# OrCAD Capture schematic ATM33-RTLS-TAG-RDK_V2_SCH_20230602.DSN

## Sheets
1 01. TITLE: title: ATM33-RTLS-TAG-RDK; rev: 0; note: <076-11-610-xxxx>
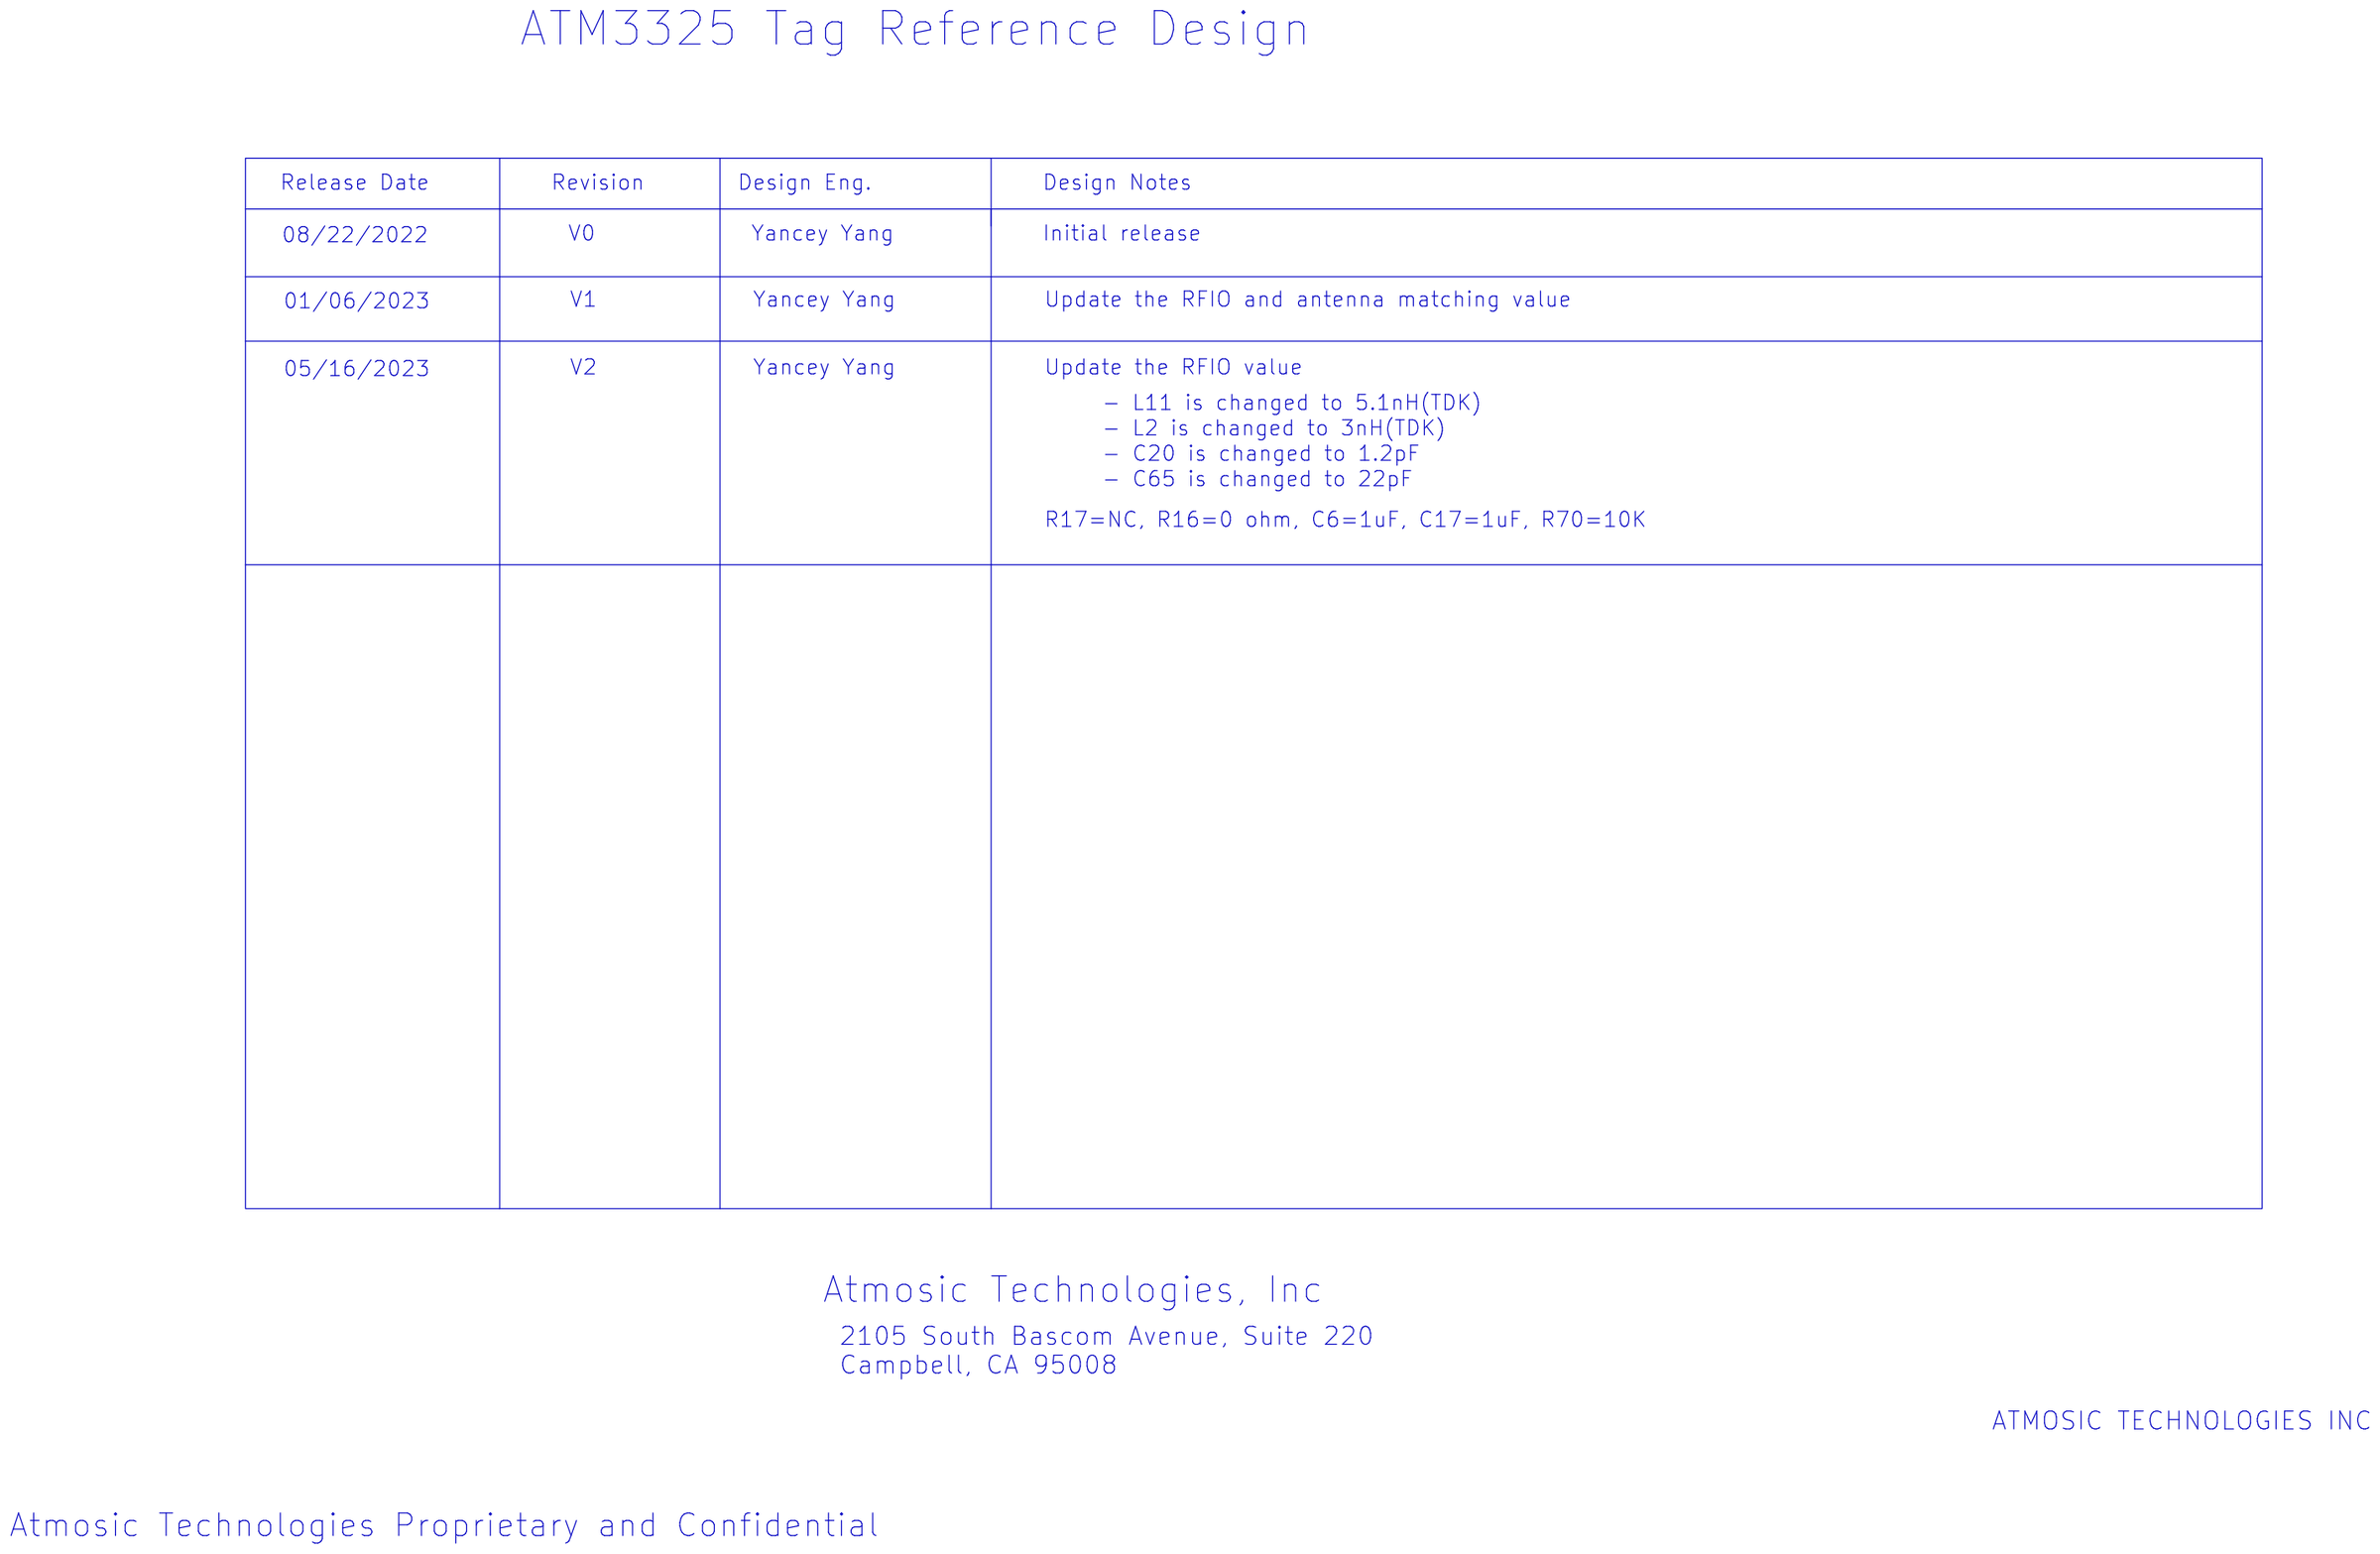
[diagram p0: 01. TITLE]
2 02_Block overall
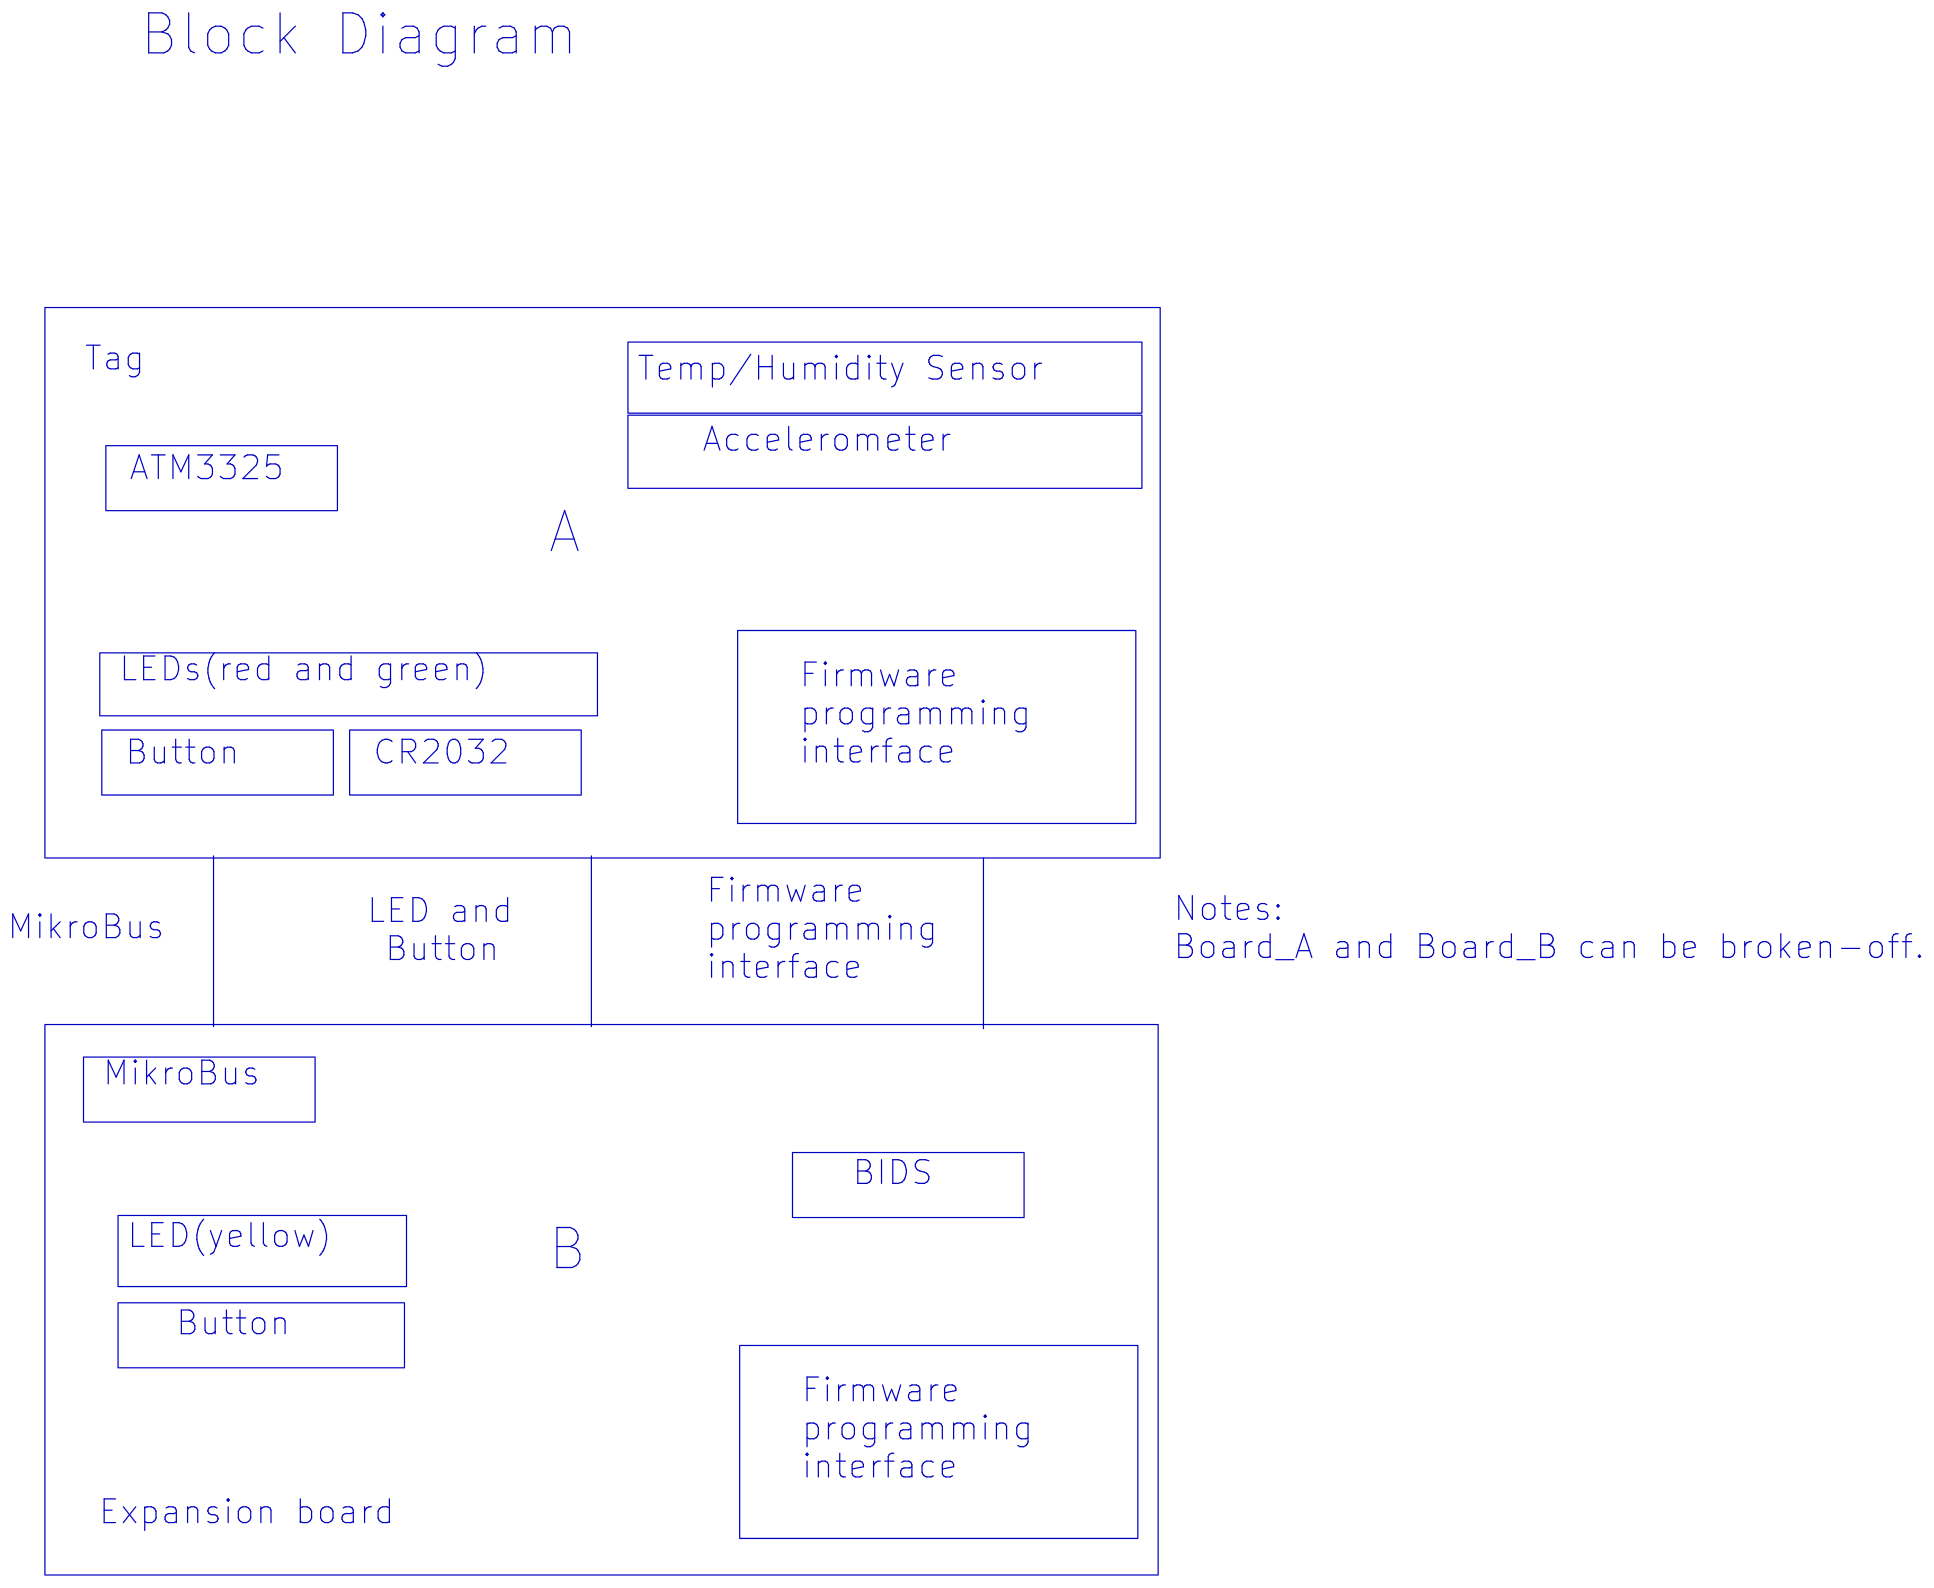
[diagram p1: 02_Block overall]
3 03. Block Diagram A
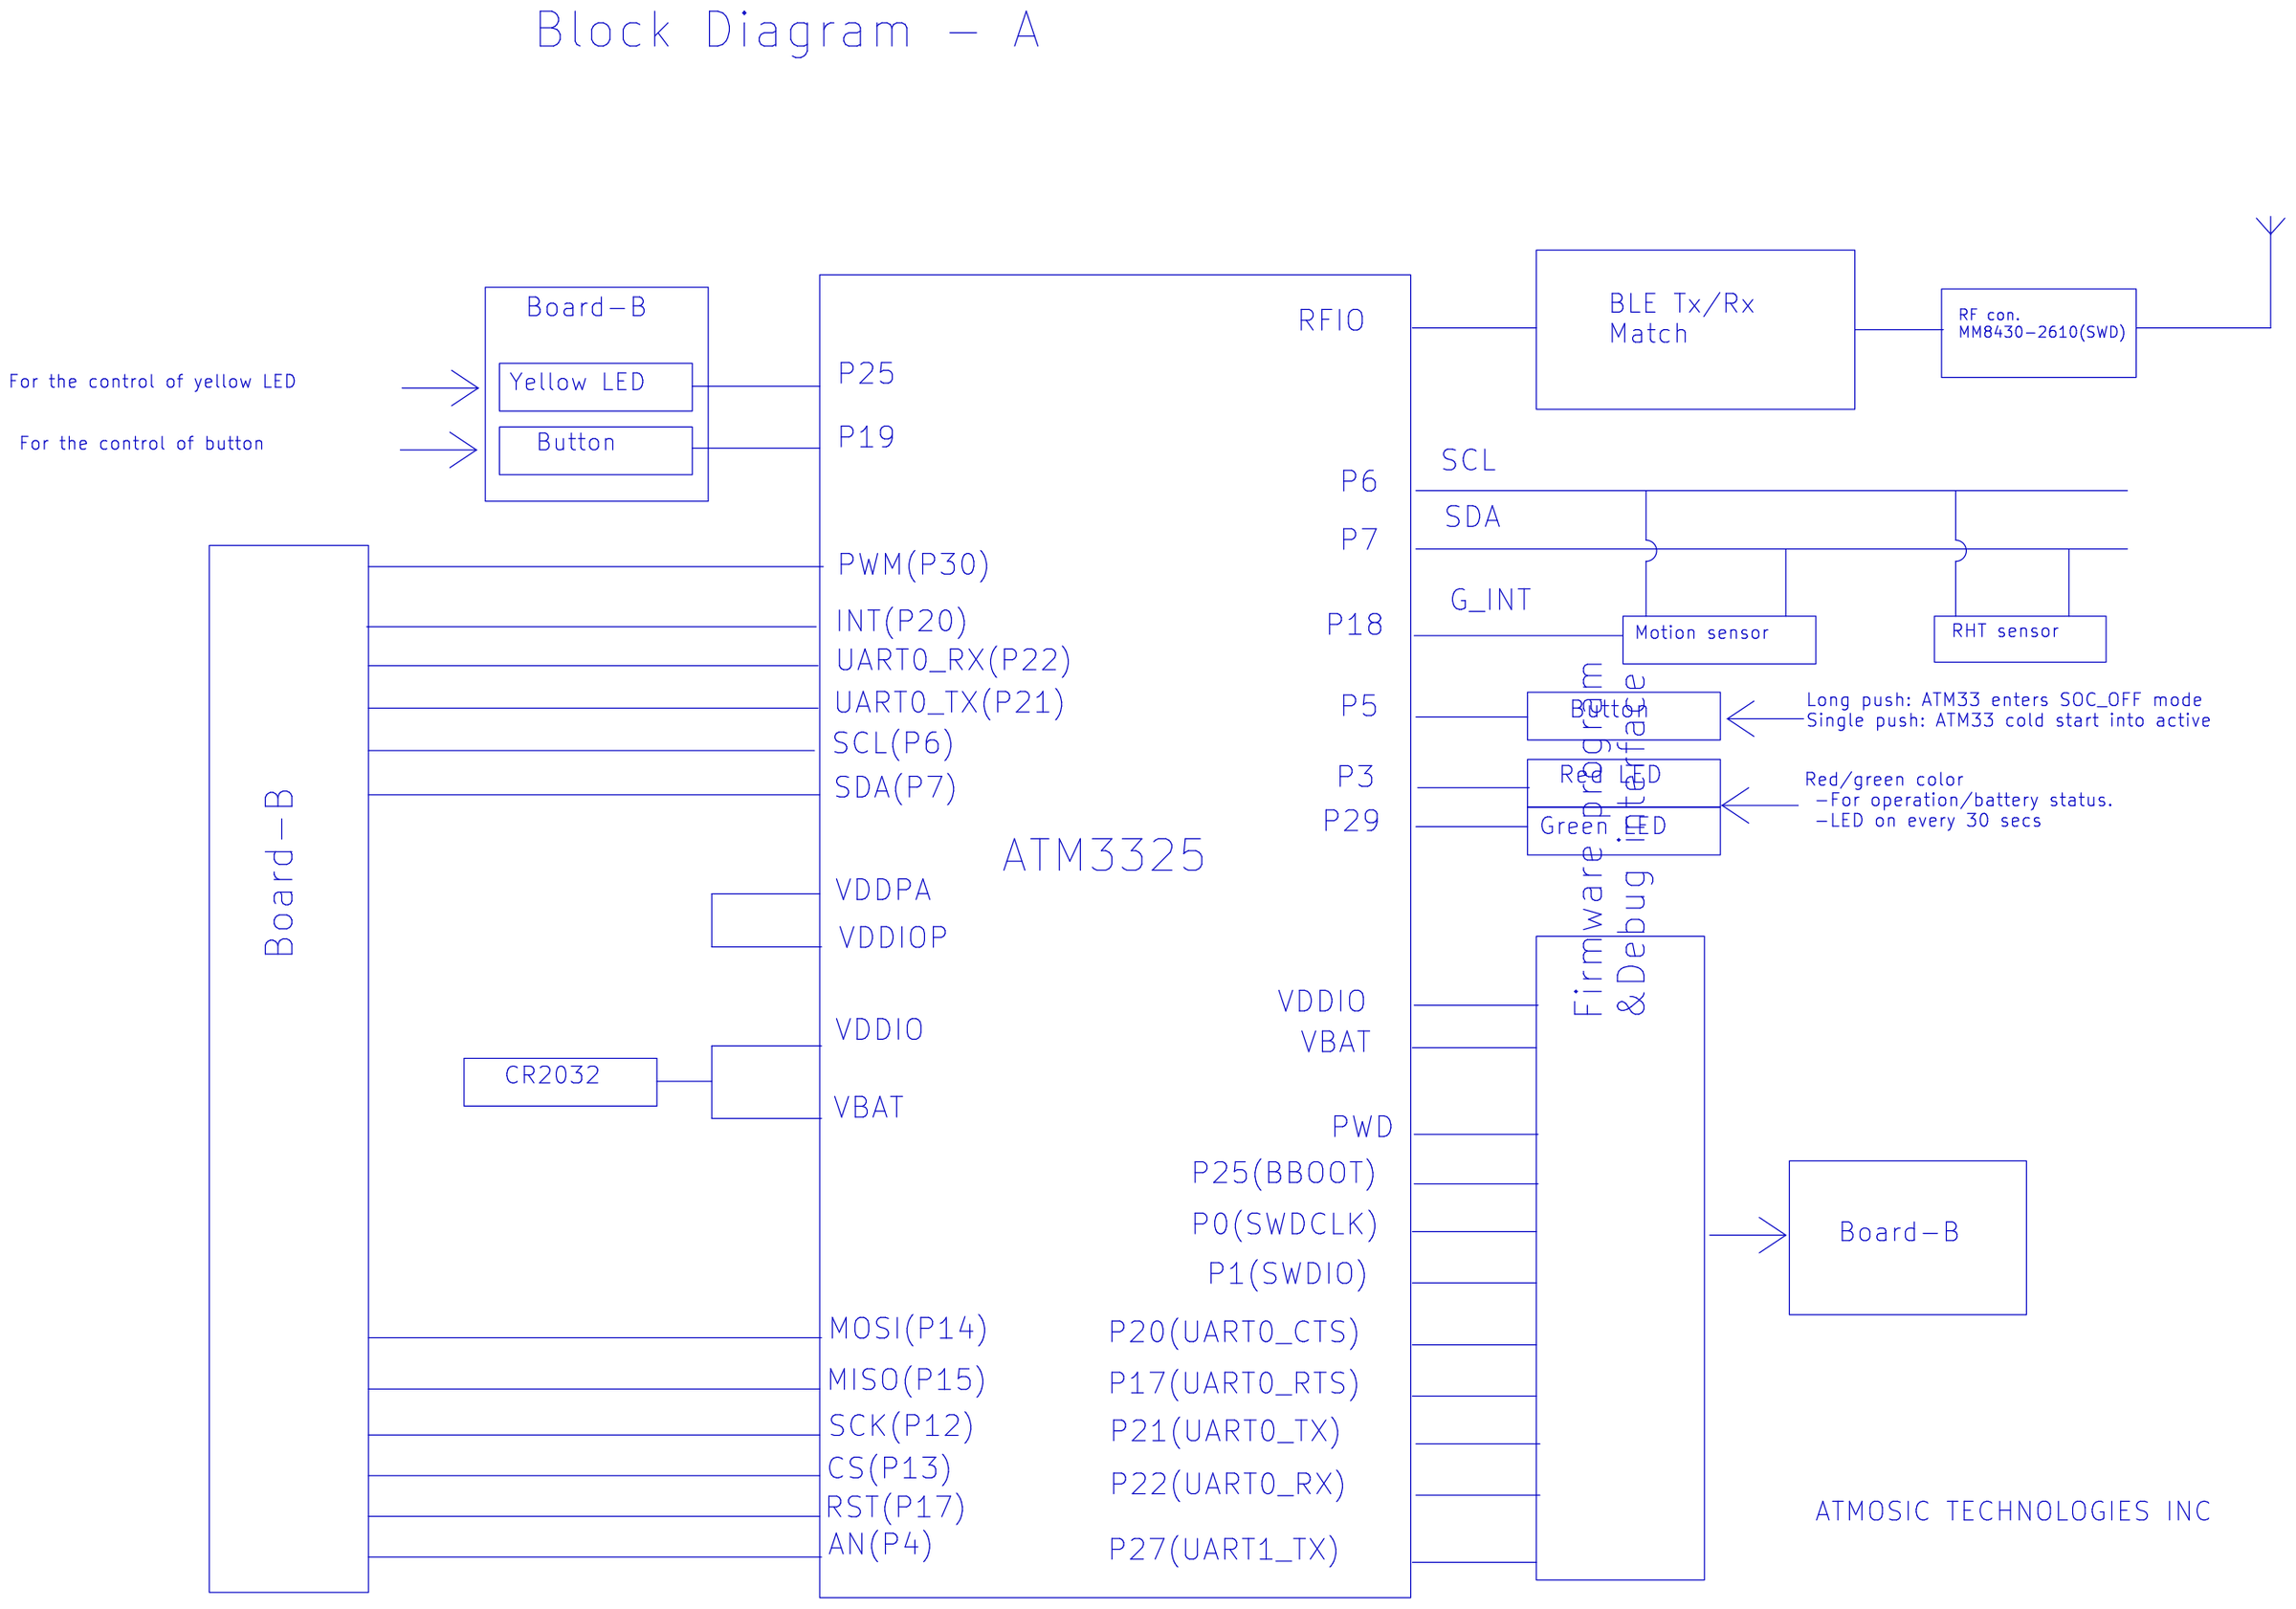
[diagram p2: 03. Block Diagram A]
4 04_Block Diagram B
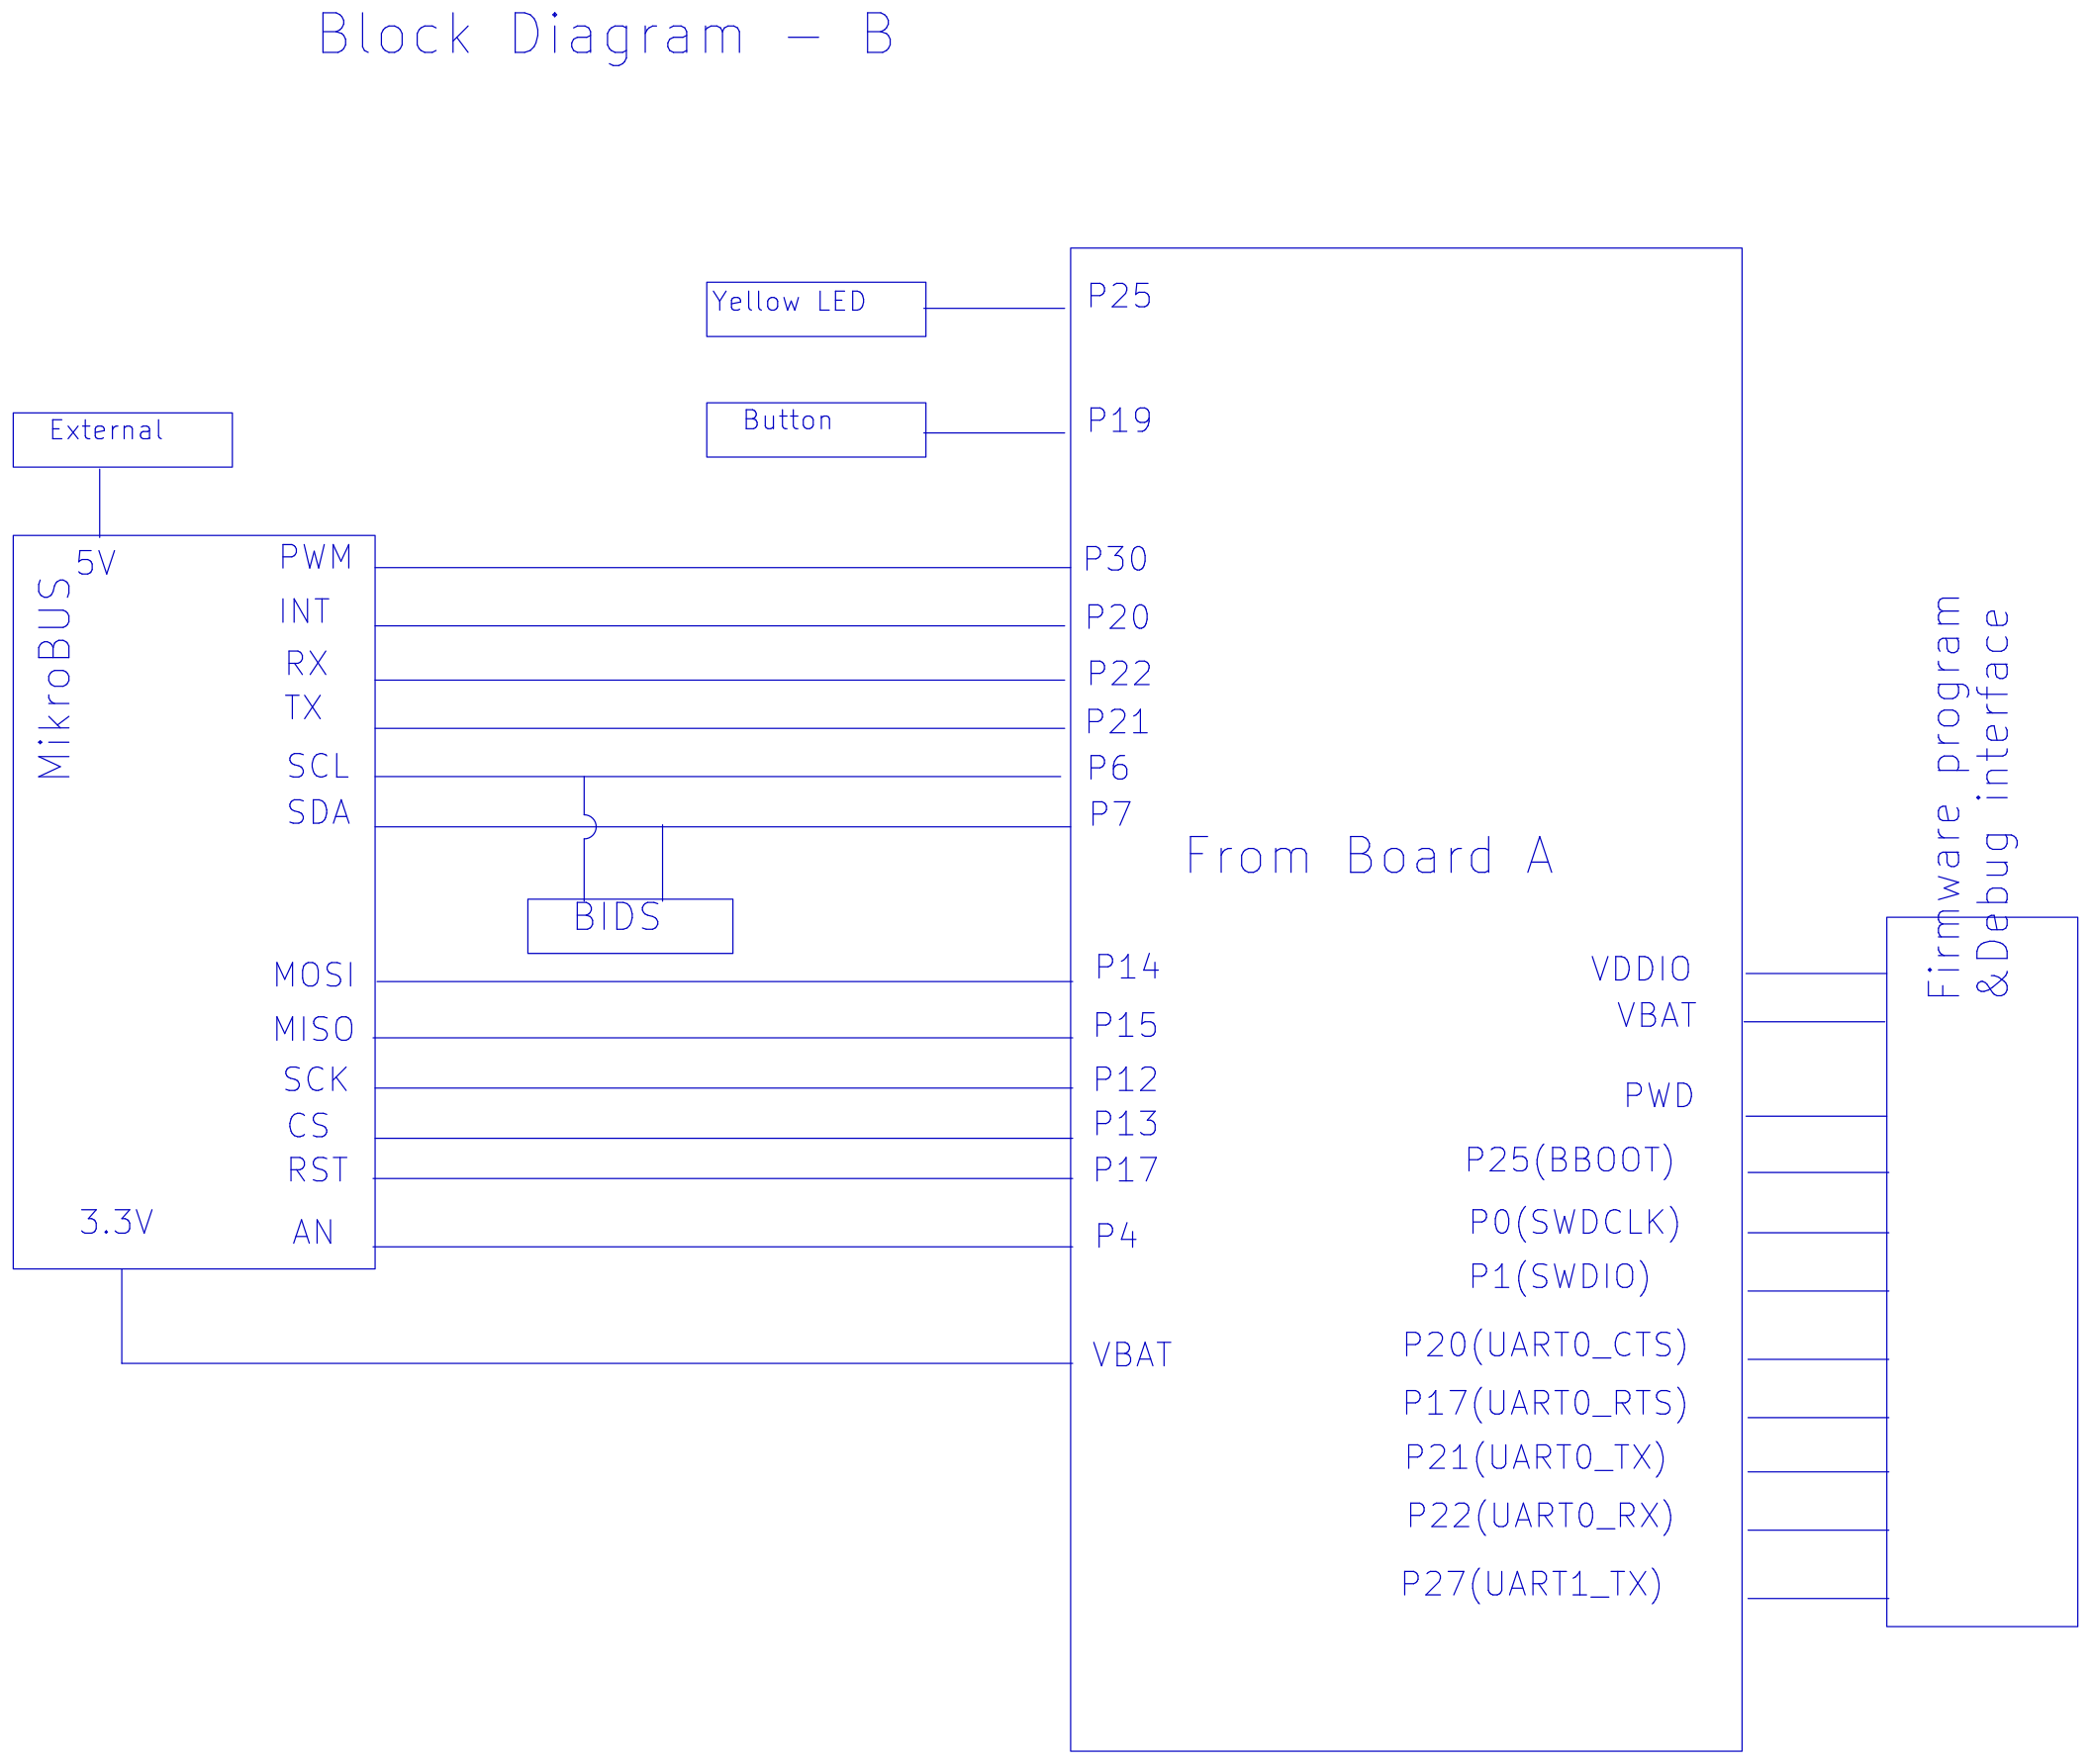
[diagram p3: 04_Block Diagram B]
5 05. ATM3325: size B; rev: 2
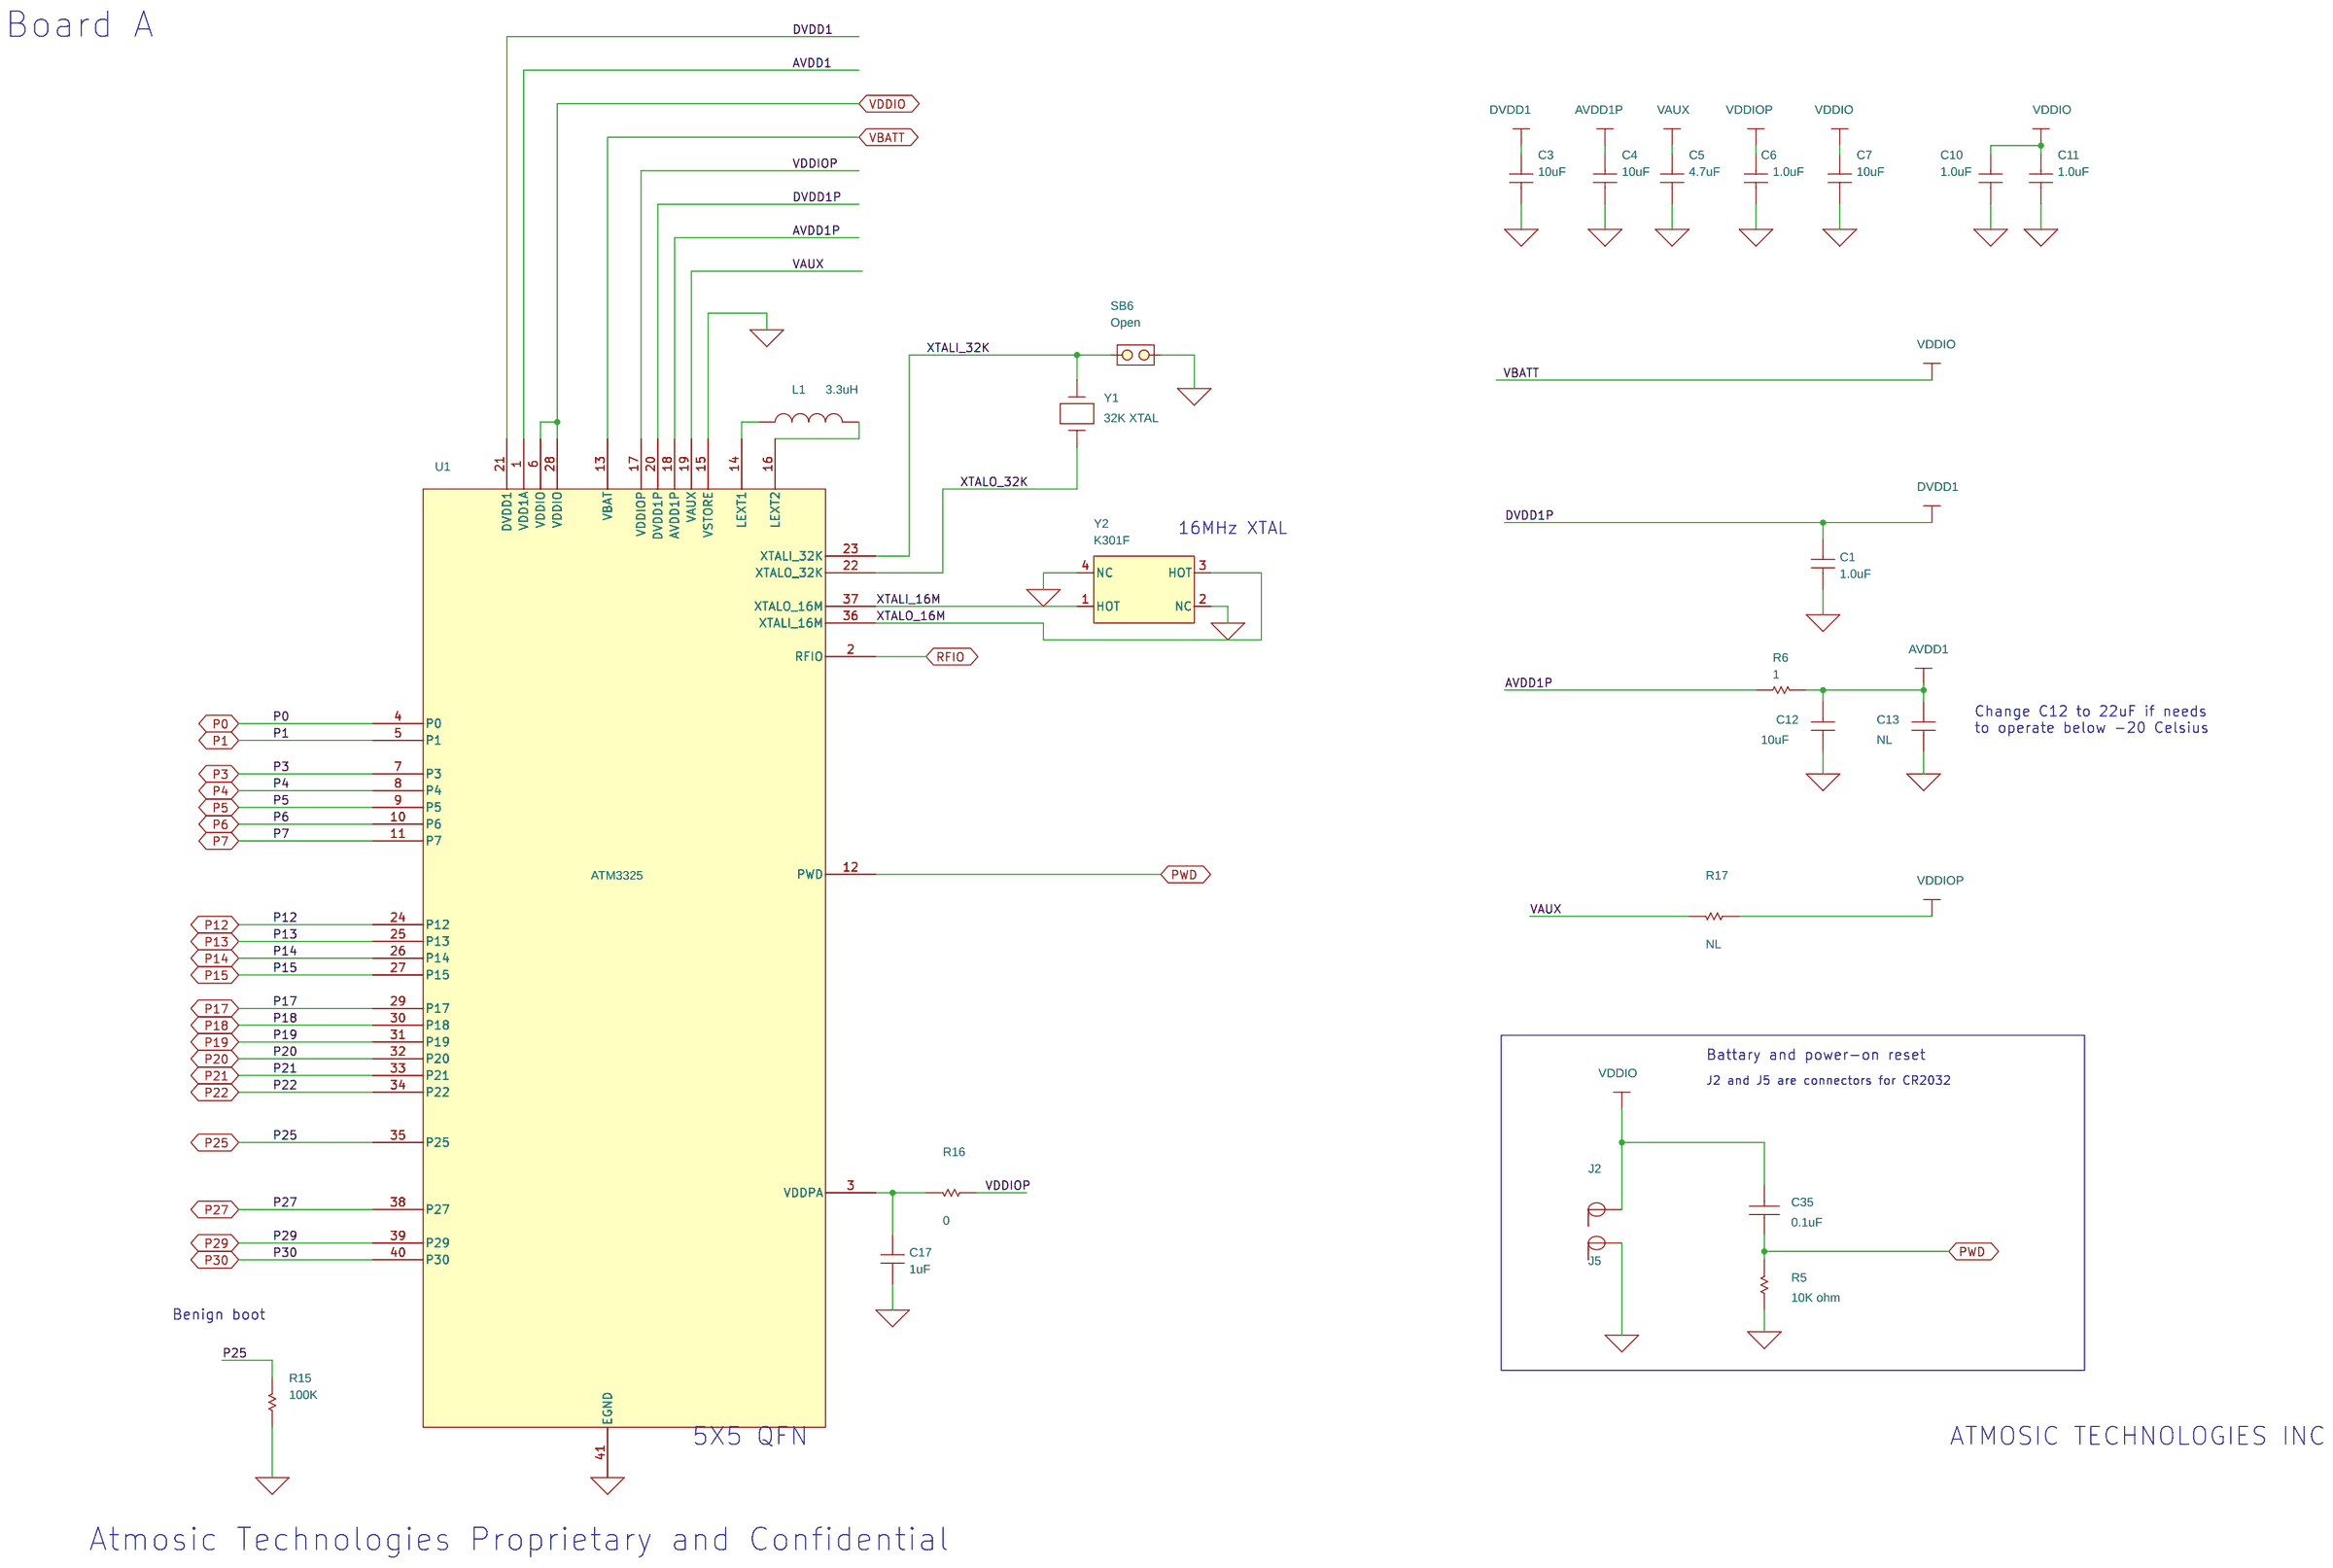
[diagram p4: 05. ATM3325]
6 06. RF (RFIO): size B
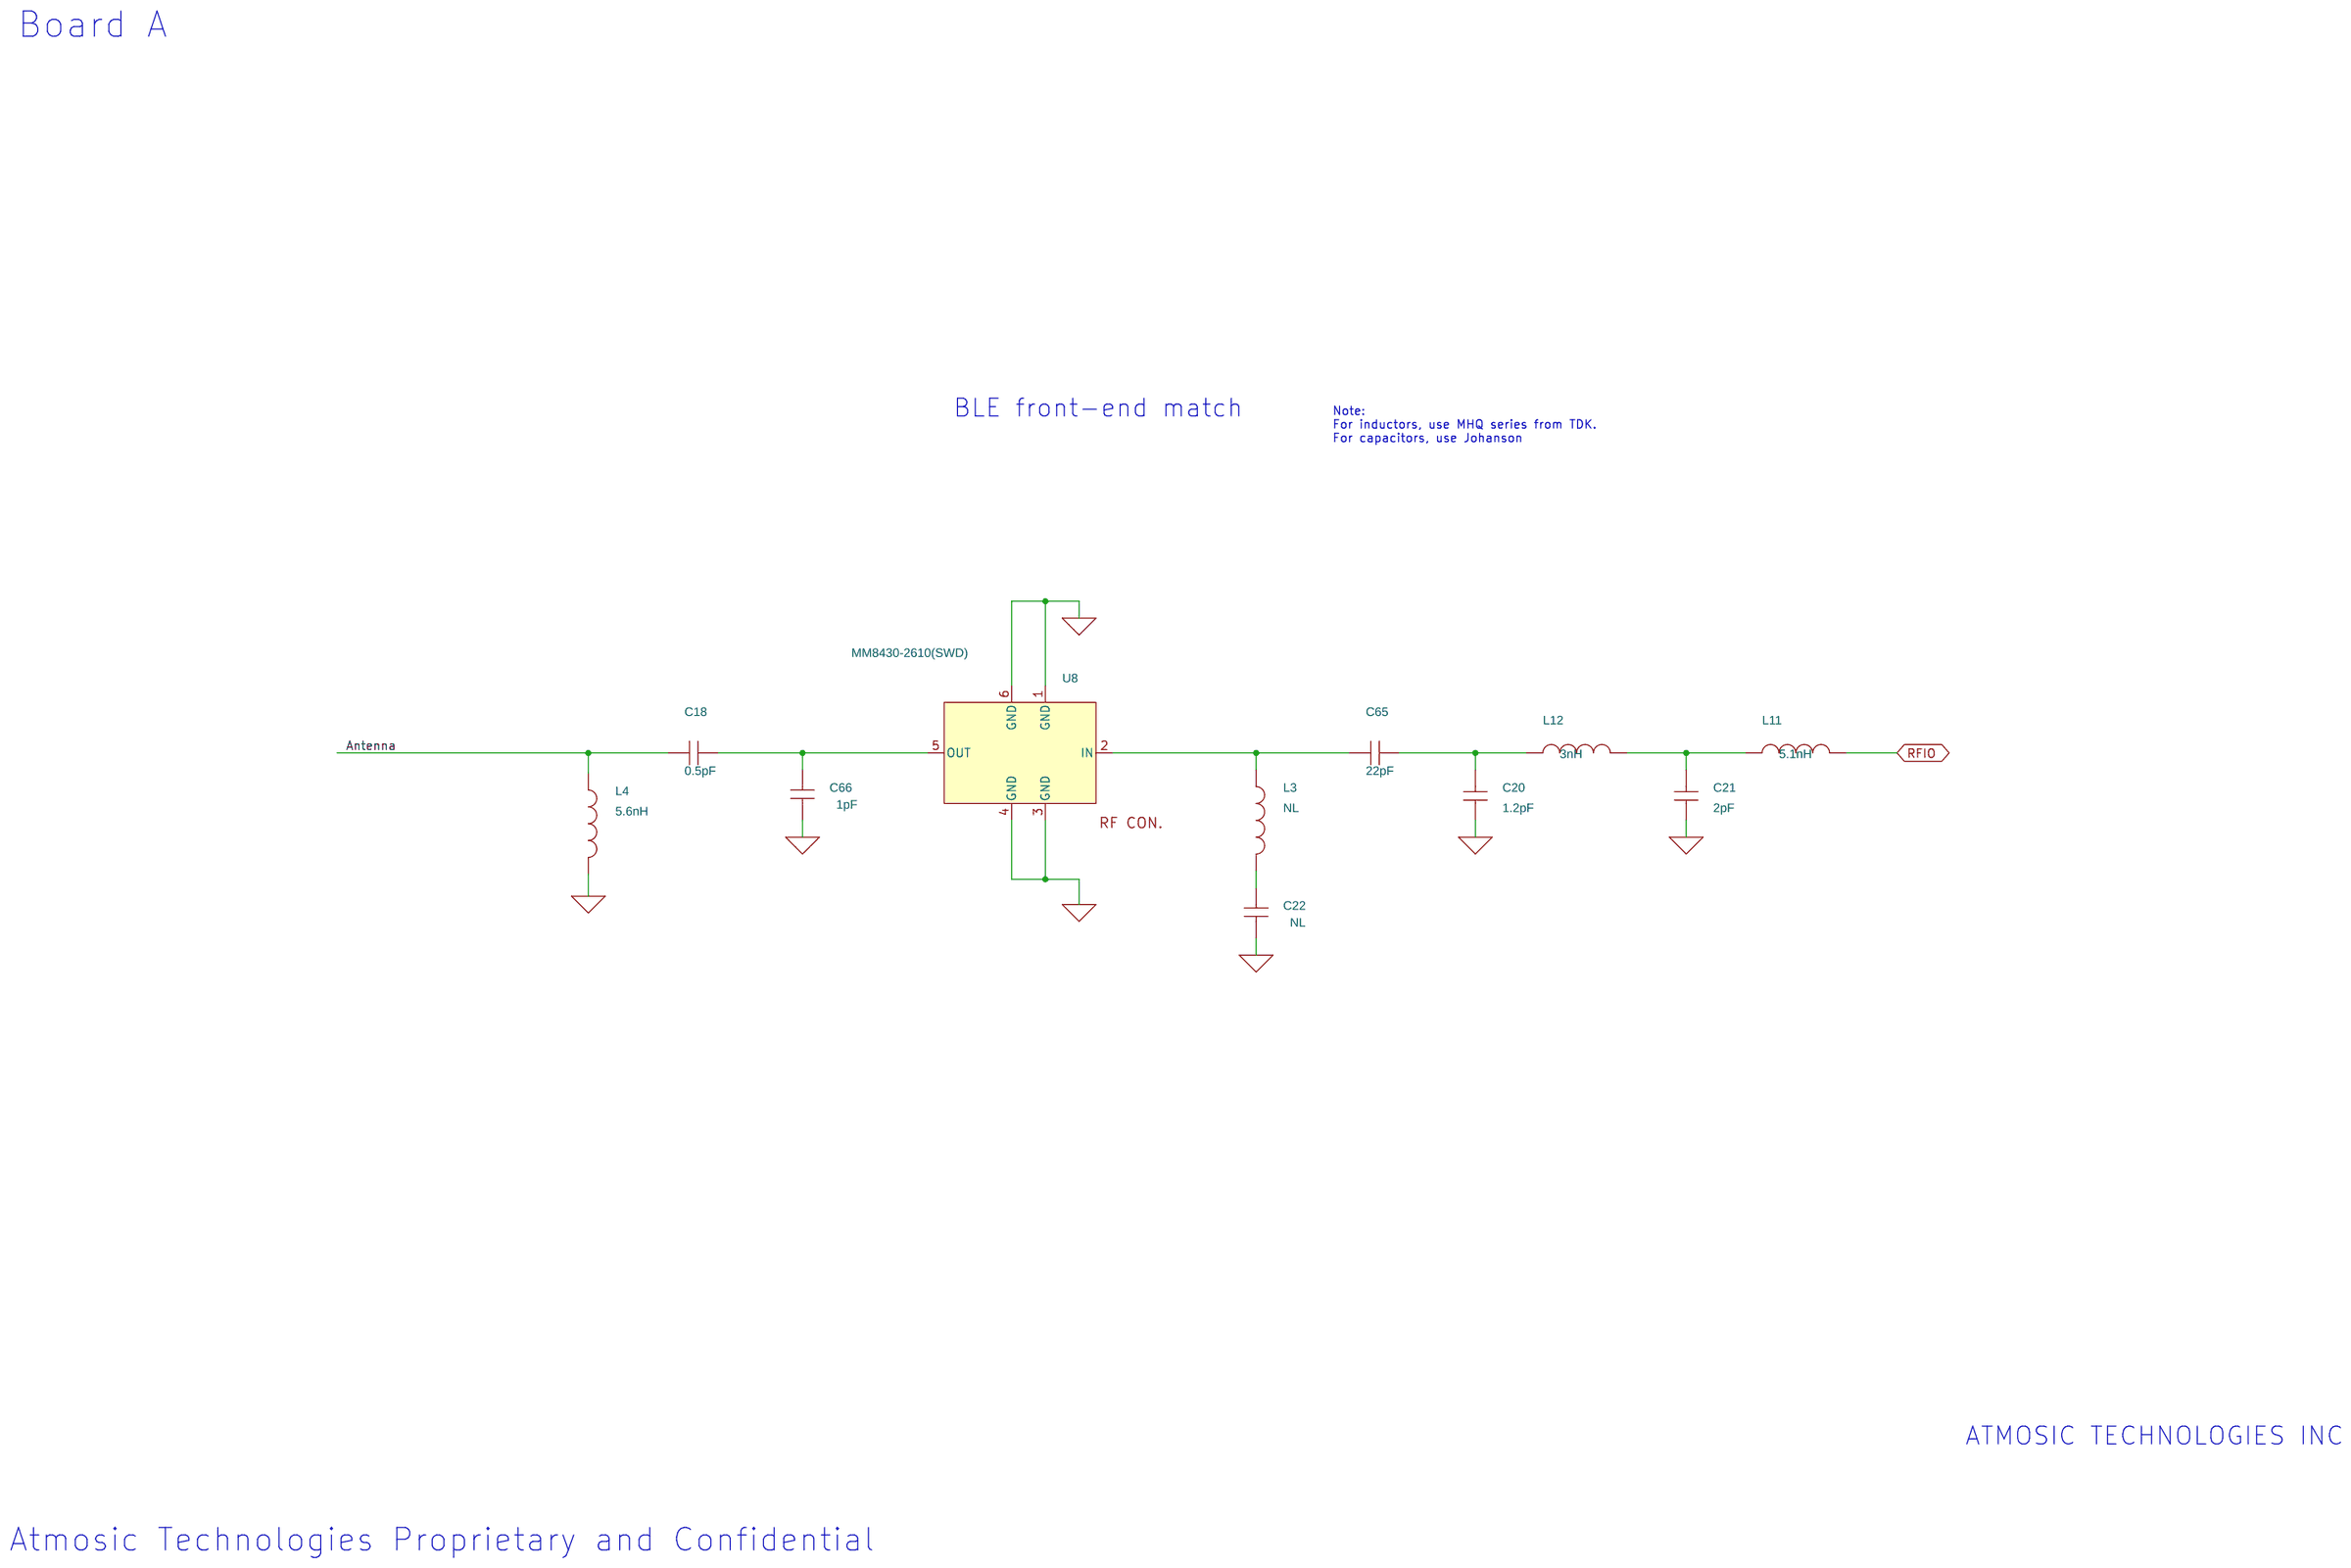
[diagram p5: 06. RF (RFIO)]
7 07. Buttons LEDs Sensors: size B
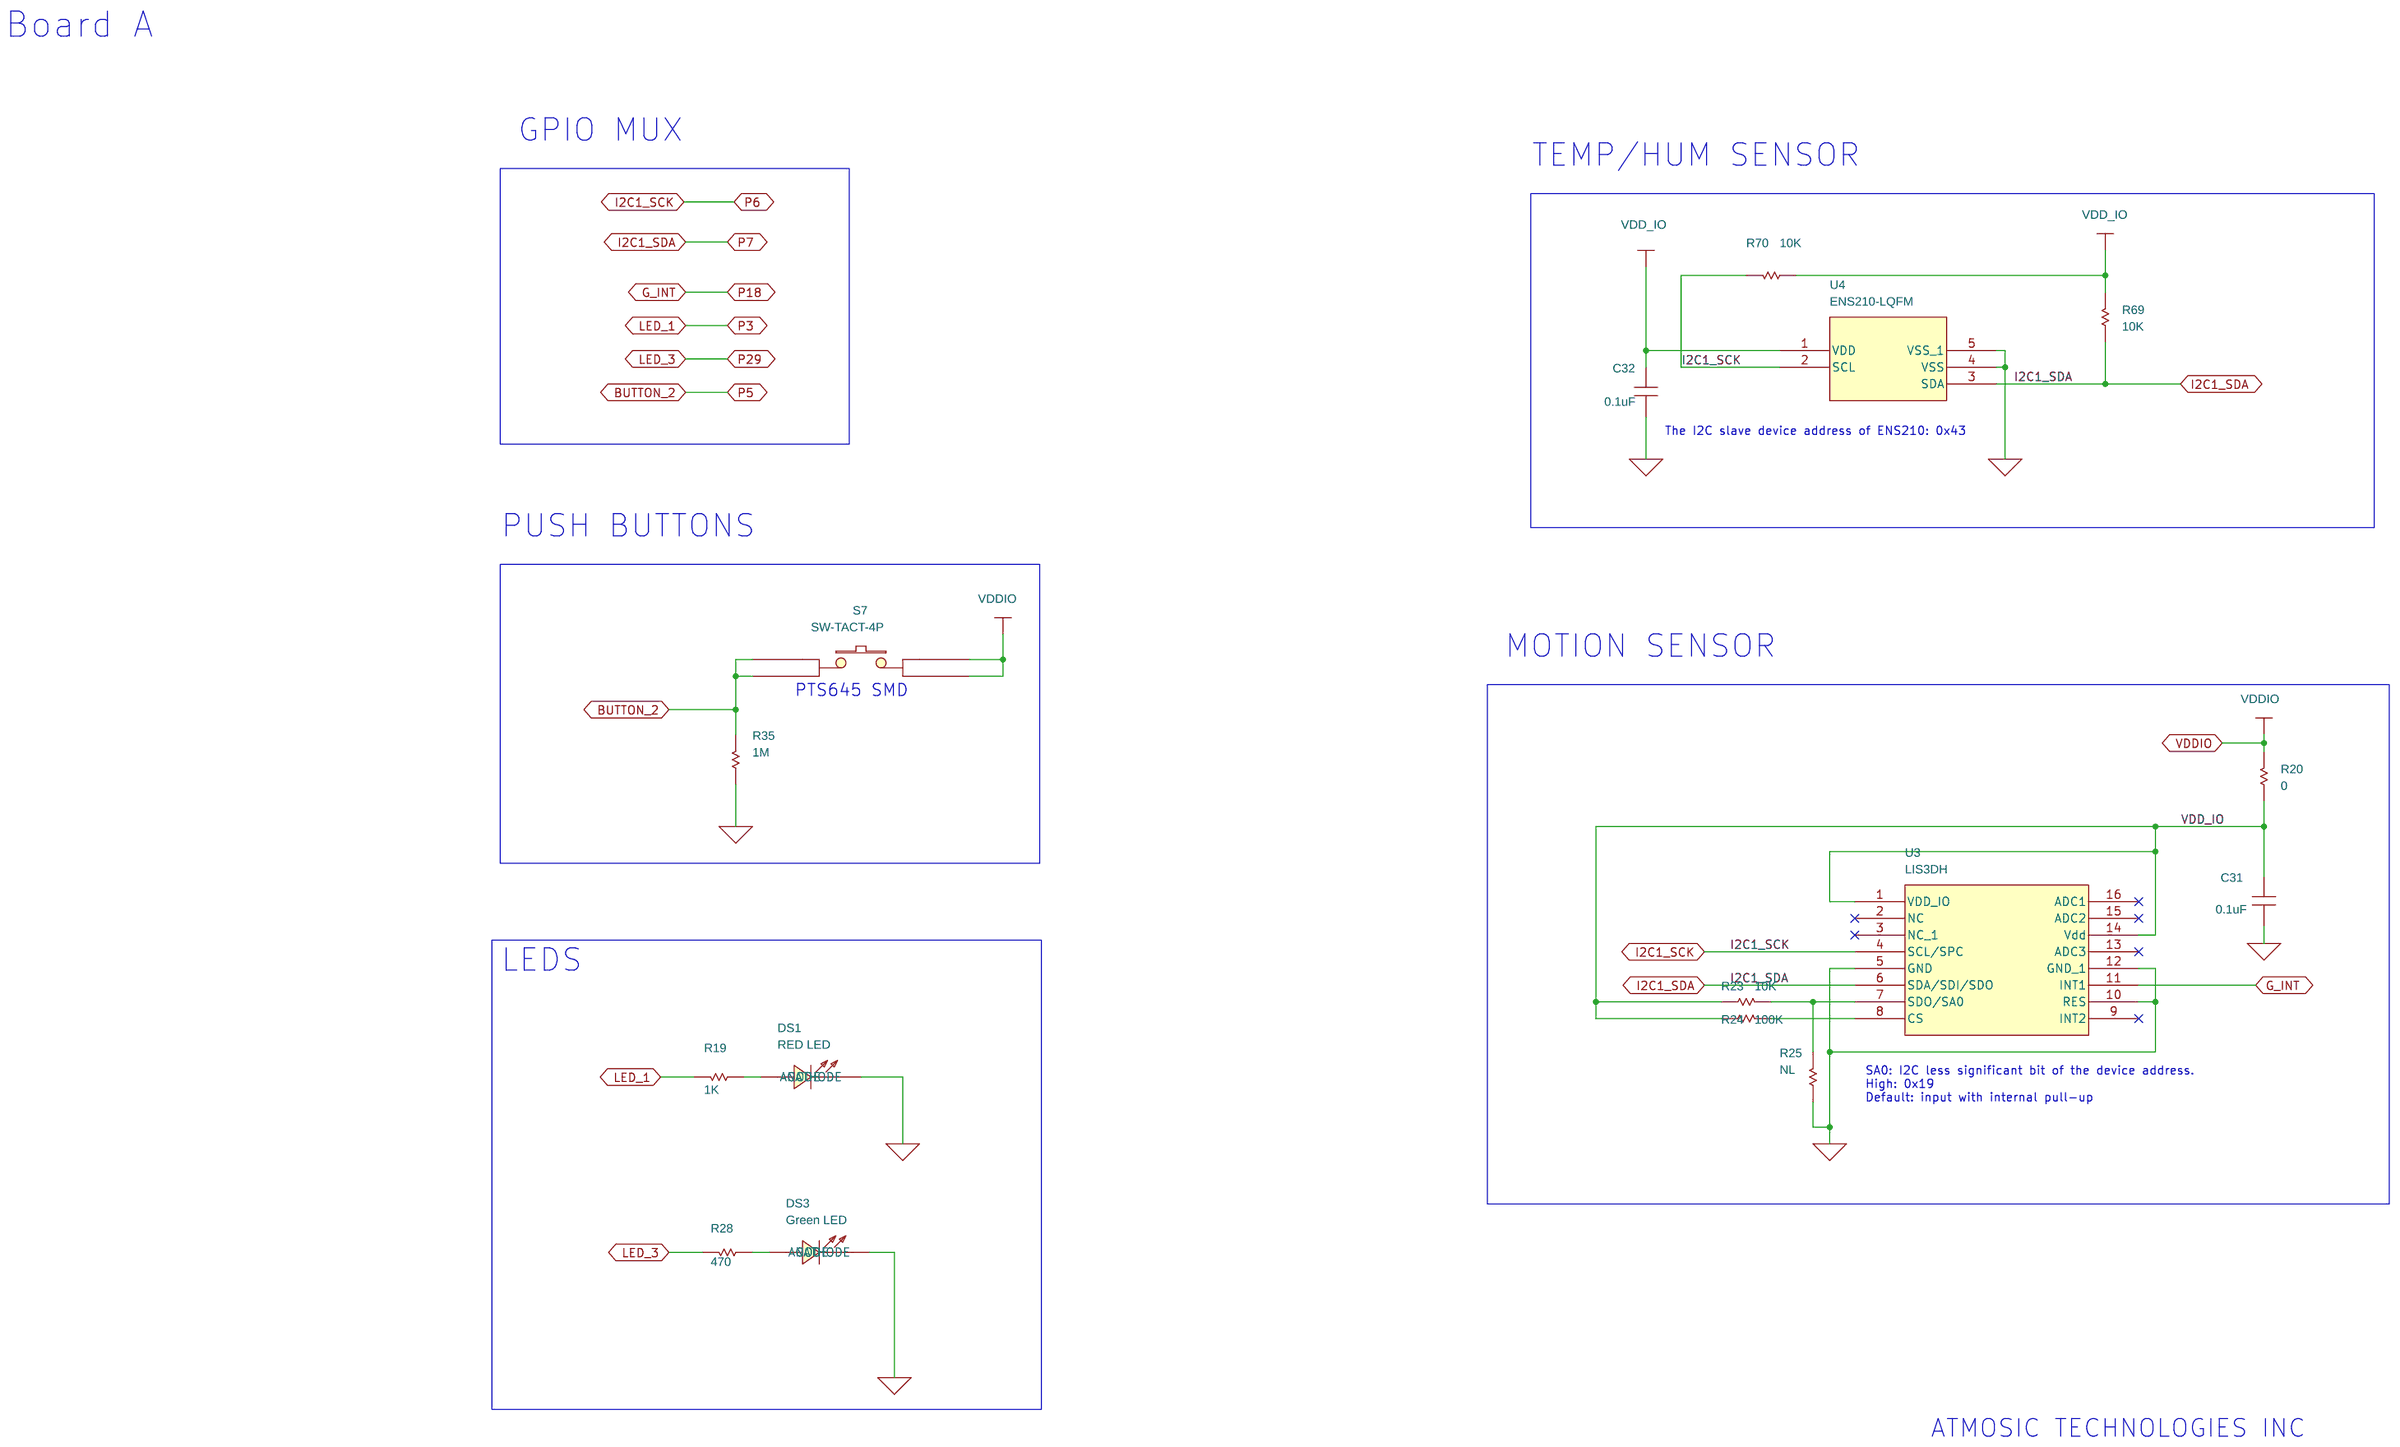
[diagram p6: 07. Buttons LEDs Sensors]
8 08. Board_A_Connectors: size B
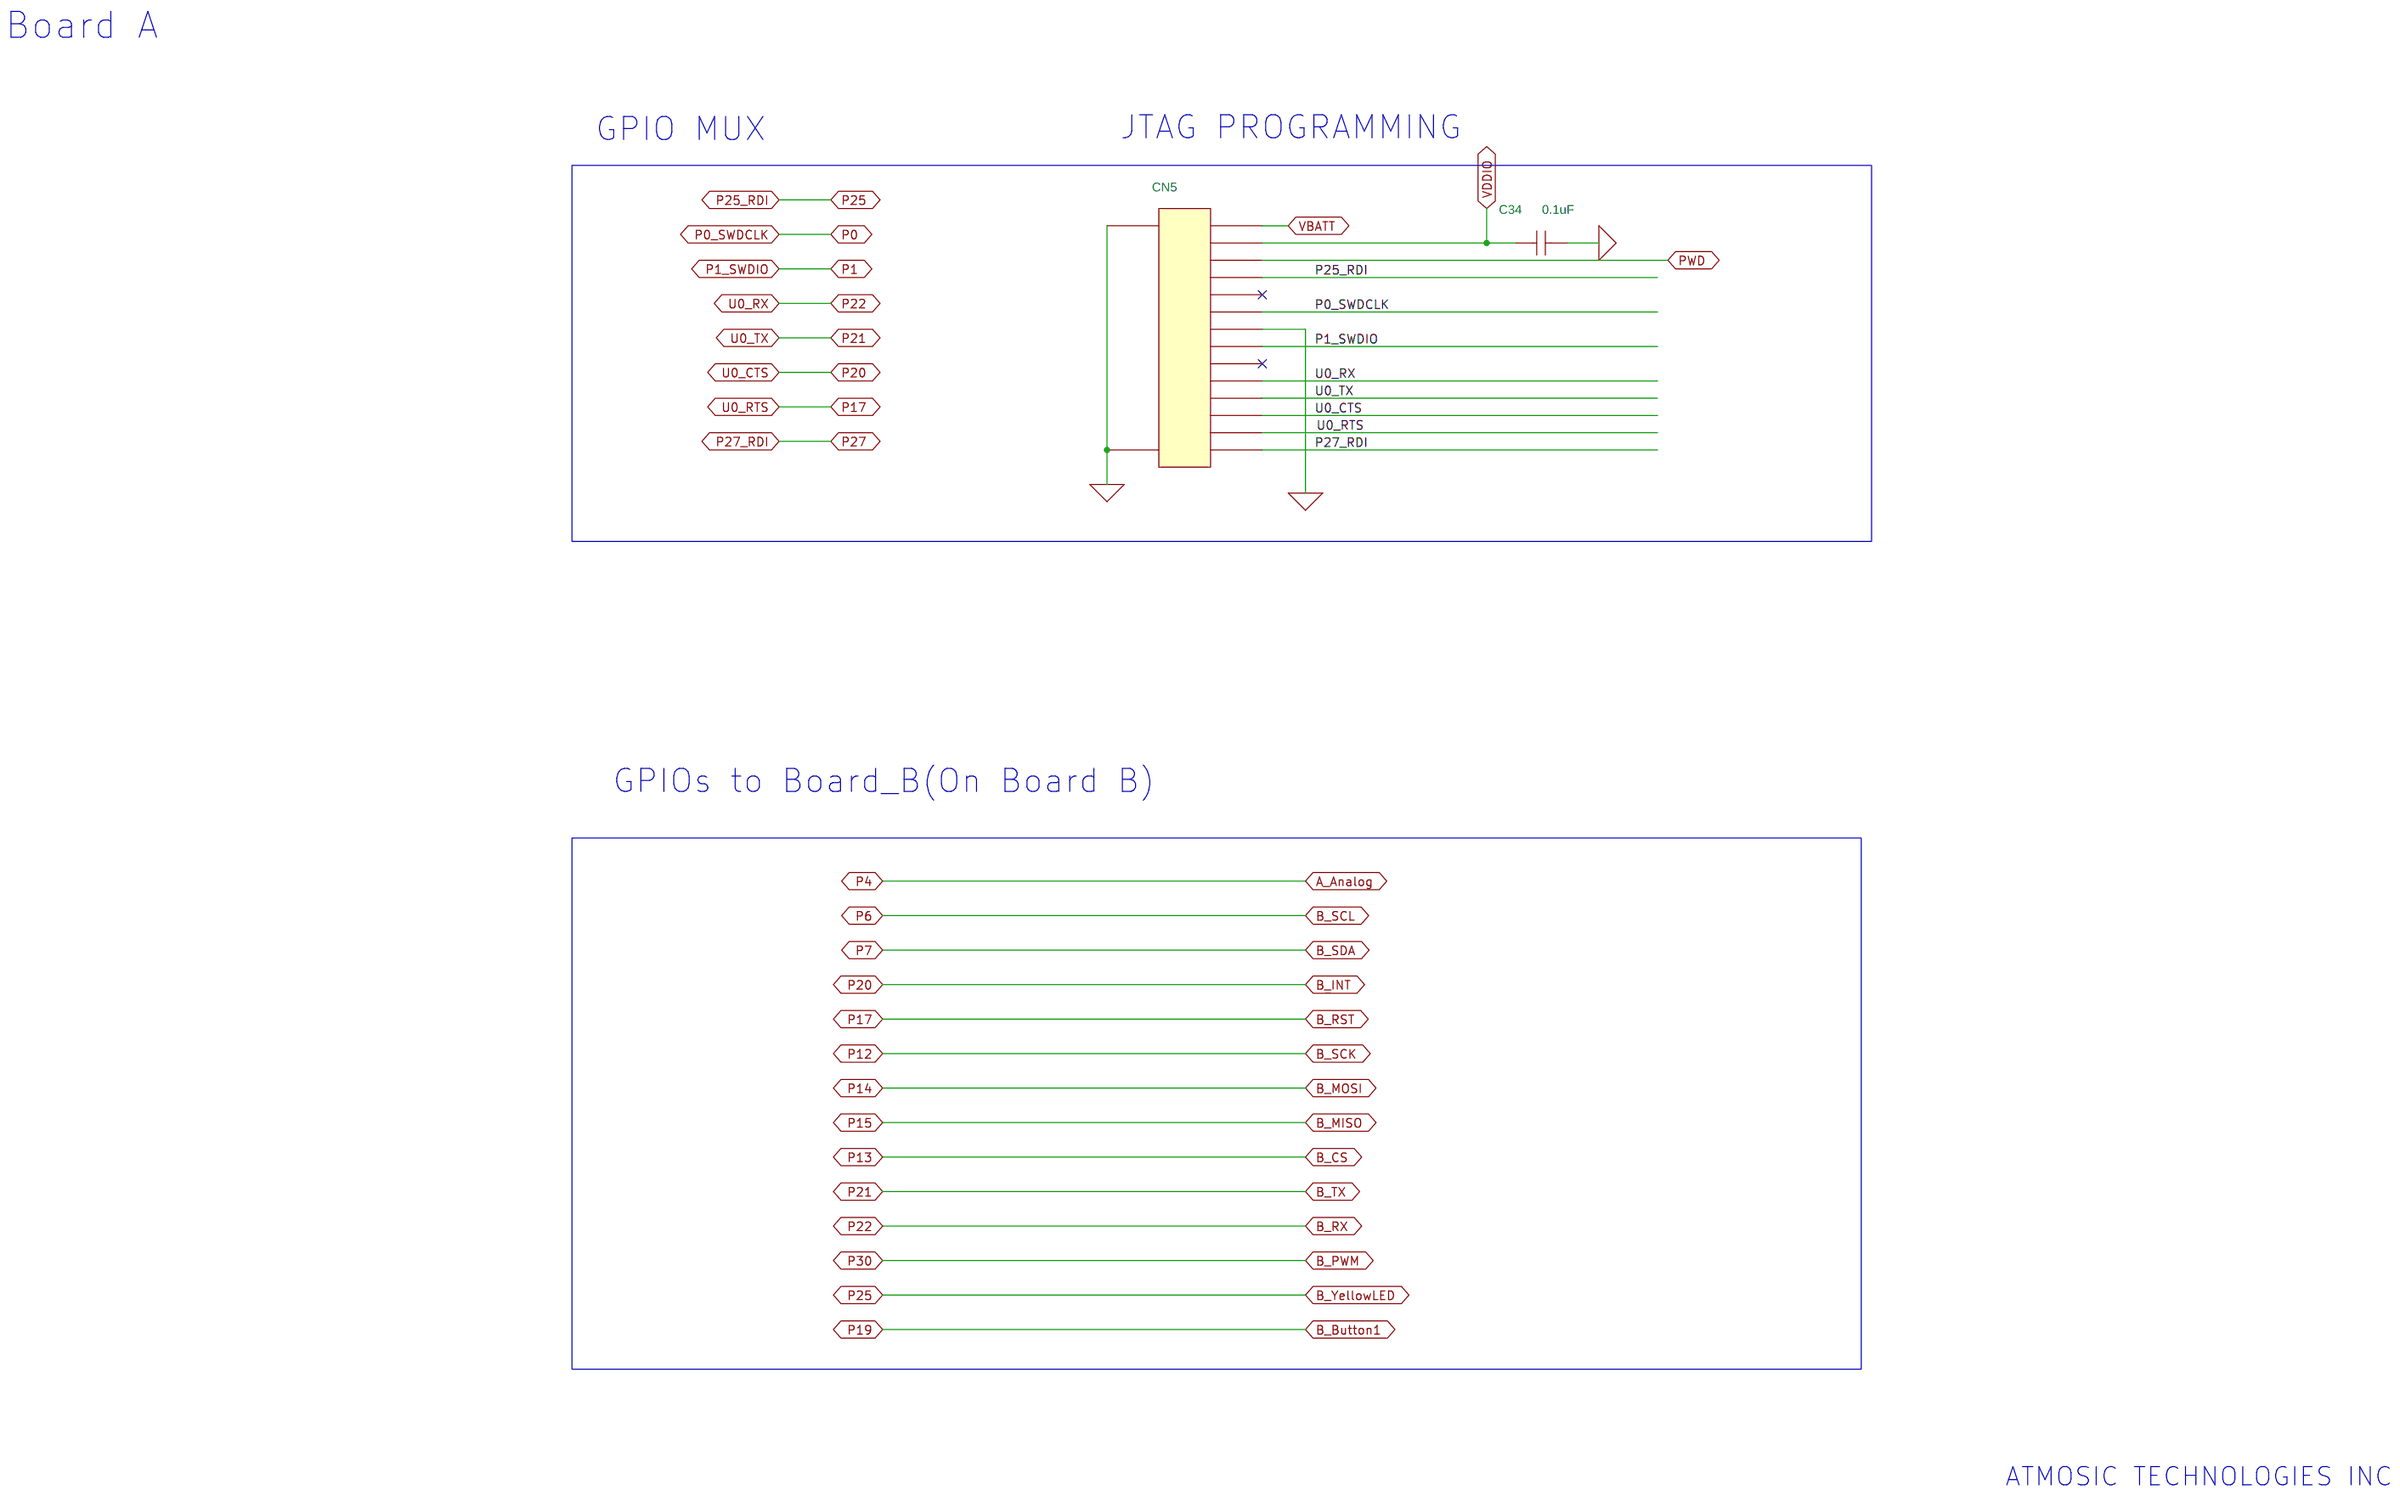
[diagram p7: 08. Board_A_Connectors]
9 09_Board_B-LEDs Buttons Sensors: size B
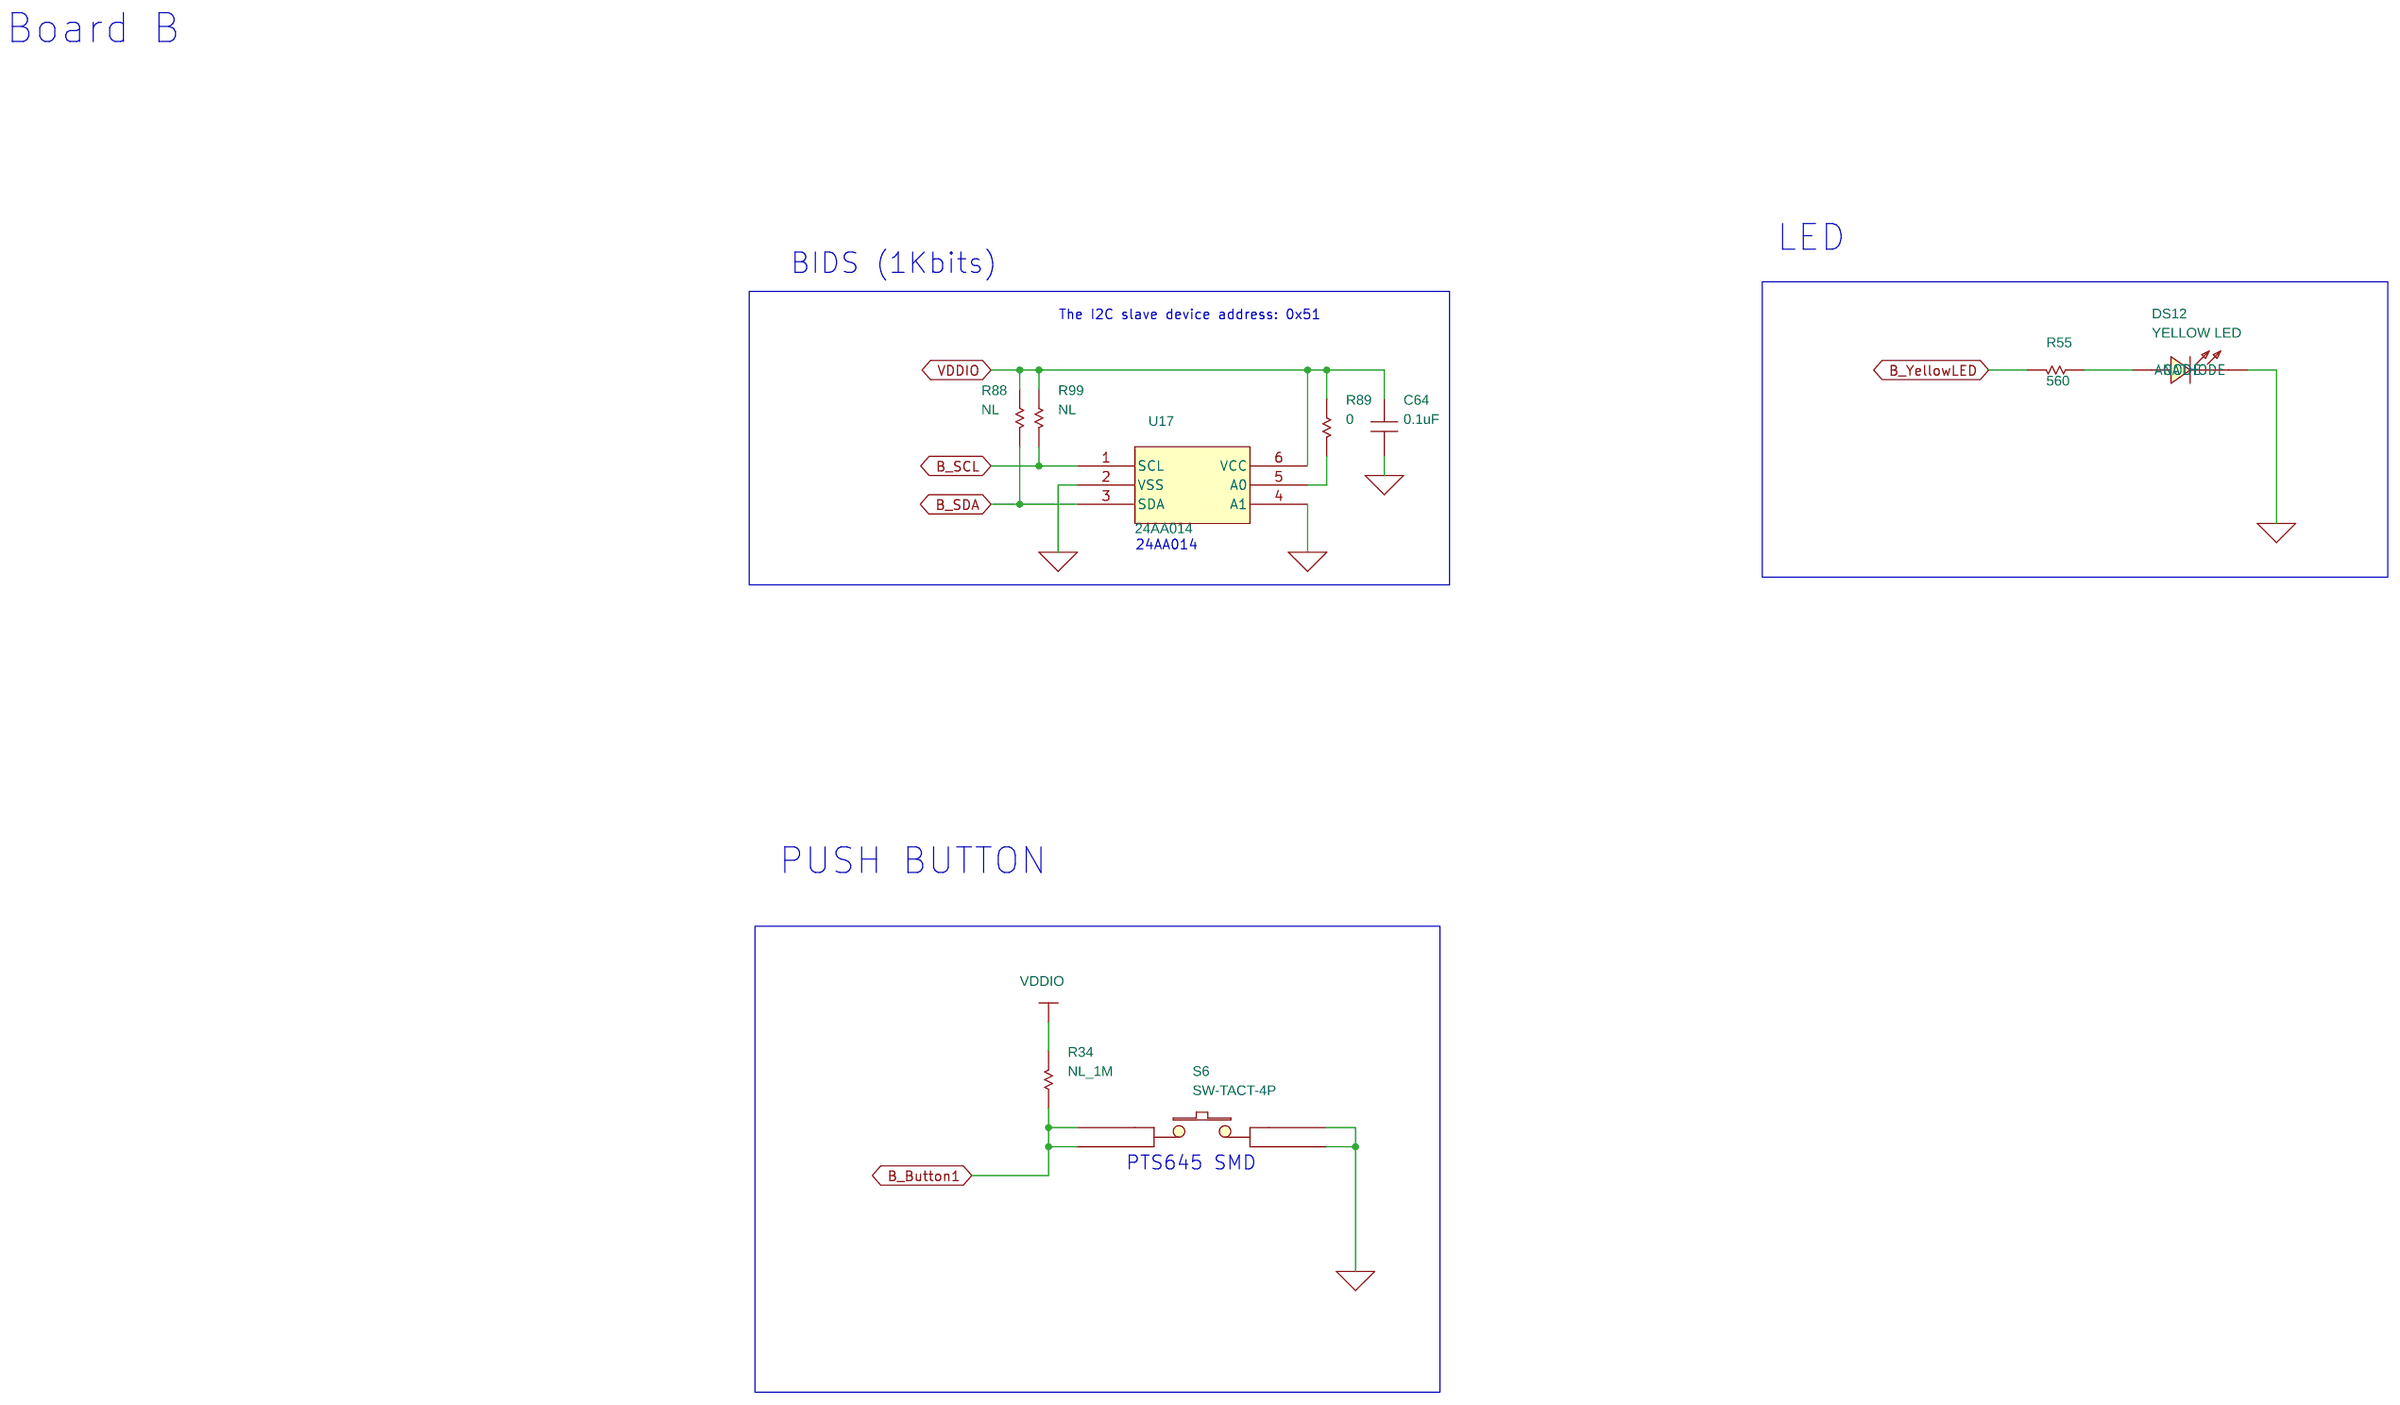
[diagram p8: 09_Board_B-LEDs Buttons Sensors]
10 10_MikroBUS Click Socket: size B; rev: A
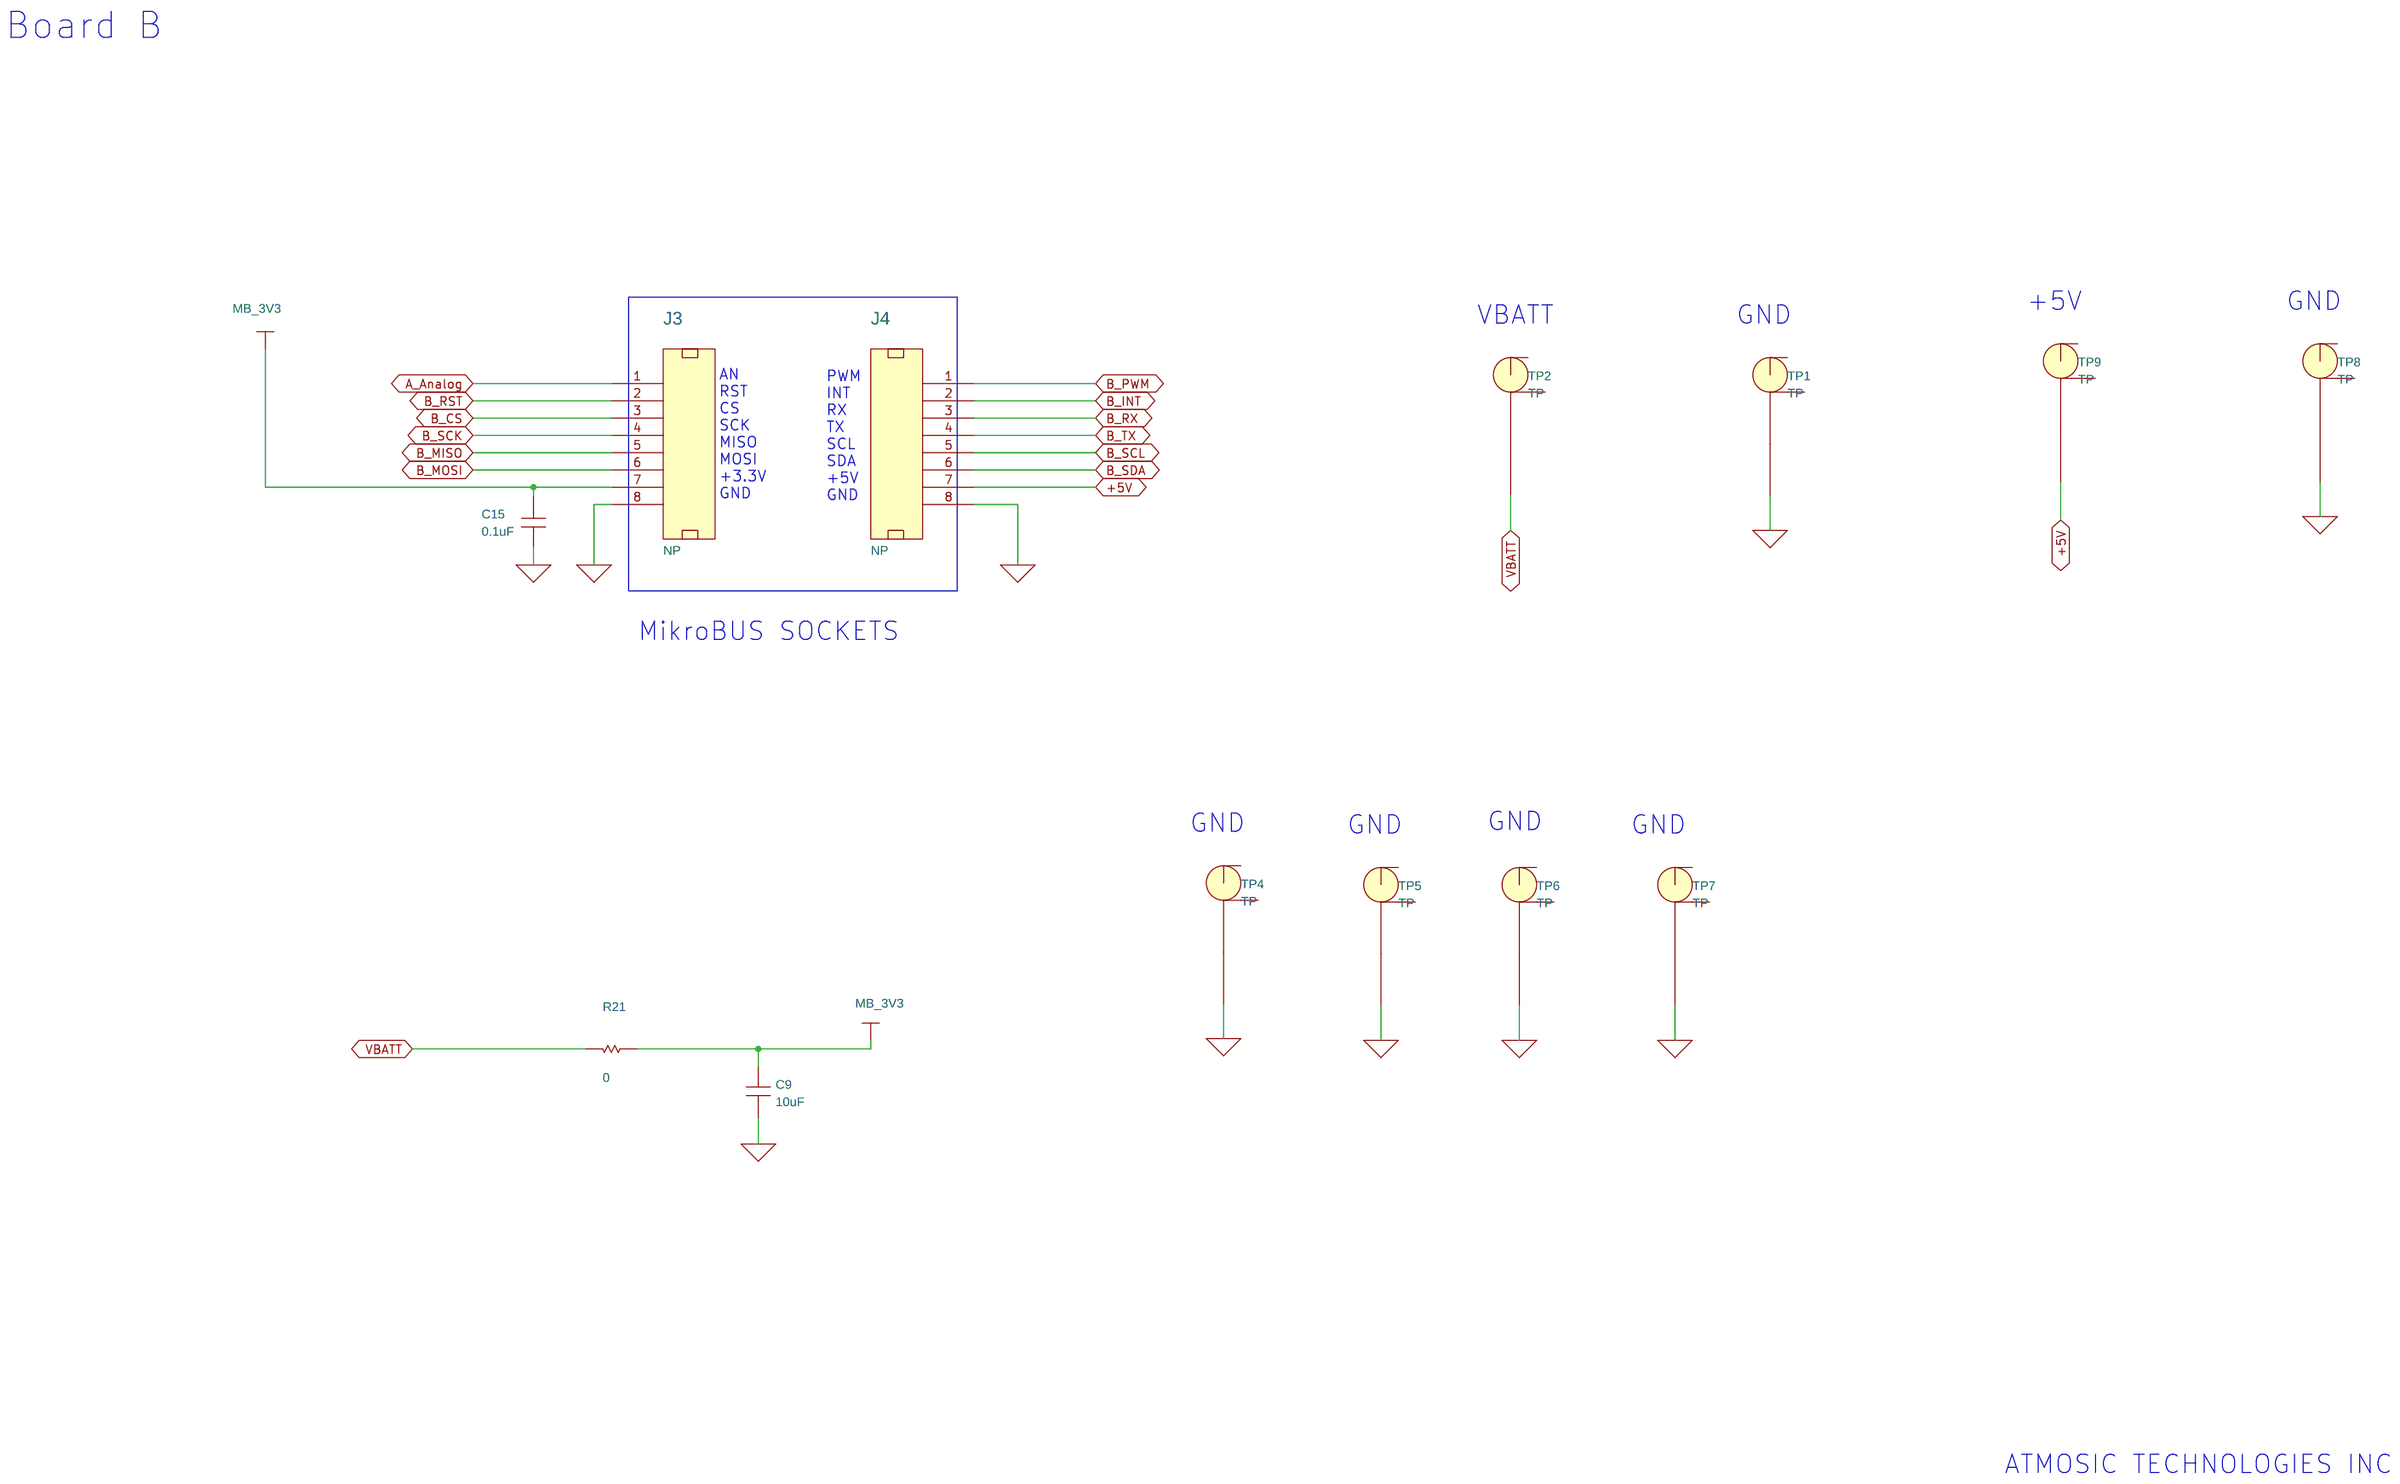
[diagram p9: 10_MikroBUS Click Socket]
11 11_Board_B_Connector: size B
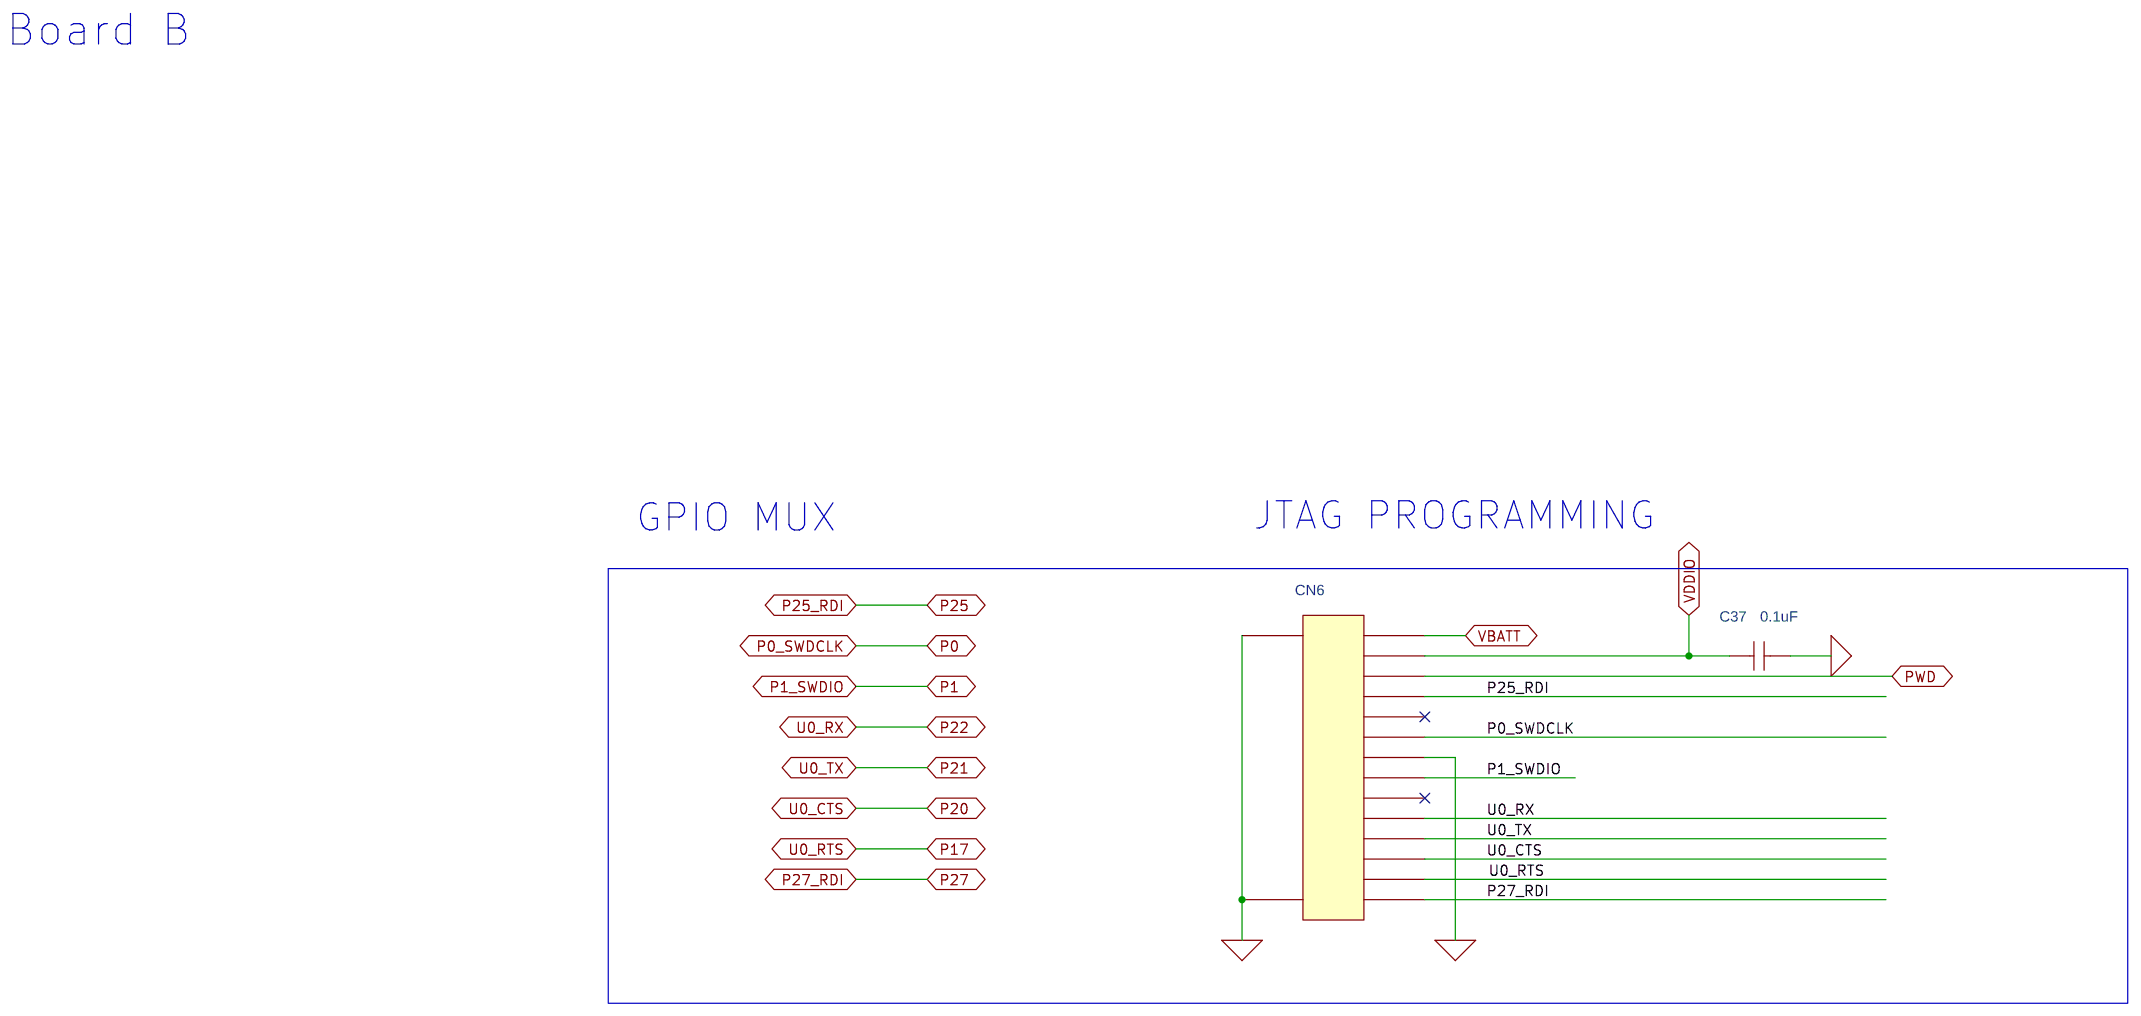
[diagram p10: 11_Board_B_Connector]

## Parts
sheet 05. ATM3325
C1  1.0uF  [0402]
C3  10uF  [0402]
C4  10uF  [0402]
C5  4.7uF  [0402]
C6  1.0uF  [0402]
C7  10uF  [0402]
C10  1.0uF  [0402]
C11  1.0uF  [0402]
C12  10uF  [0603]
C13  NL  [0603]
C17  1uF  [0402]
C35  0.1uF  [0402]
J2  TP  [BATTERY+]
J5  TP  [BATTERY-]
L1  3.3uH  [IND-2016-2]
R5  10K ohm  [0402]
R6  1  [0402]
R15  100K  [0402]
R16  0  [0201]
R17  NL  [0201]
SB6  Open  [0402]
U1  ATM3325  [QFN-40-5X5-0.4MM]
Y1  32K XTAL  [XTAL-SMD2-2.0X1.2MM]
Y2  K301F  [XTAL-ECX-2236]
sheet 06. RF (RFIO)
C18  0.5pF  [0201]
C20  1.2pF  [0201]
C21  2pF  [0201]
C22  NL  [0201]
C65  22pF  [0201]
C66  1pF  [0201]
L3  NL  [0201]
L4  5.6nH  [0201]
L11  5.1nH  [0201]
L12  3nH  [0201]
U8  MM8430-2610(SWD)  [RF_SWD]
sheet 07. Buttons LEDs Sensors
C31  0.1uF  [0402]
C32  0.1uF  [0402]
DS1  RED LED  [LED-0603]
DS3  Green LED  [LED-0603]
R19  1K  [0402]
R20  0  [0402]
R23  10K  [0402]
R24  100K  [0402]
R25  NL  [0402]
R28  470  [0402]
R35  1M  [0402]
R69  10K  [0402]
R70  10K  [0402]
S7  SW-TACT-4P  [SW_TAG]
U3  LIS3DH  [LGA-16-3X3]
U4  ENS210-LQFM  [SON-04-2X2MM]
sheet 08. Board_A_Connectors
C34  0.1uF  [0402]
CN5  05002HR-14CE  [FFC/0.5mm/14PIN]
sheet 09_Board_B-LEDs Buttons Sensors
C64  0.1uF  [0402]
DS12  YELLOW LED  [LED-0603]
R34  NL_1M  [0402]
R55  560  [0402]
R88  NL  [0402]
R89  0  [0402]
R99  NL  [0402]
S6  SW-TACT-4P  [SWI-SM-PTS645]
U17  24AA014  [SOT23-6]
sheet 10_MikroBUS Click Socket
C9  10uF  [0402]
C15  0.1uF  [0402]
J3  NP  [HEADER1X8_2P54]
J4  NP  [HEADER1X8_2P54]
R21  0  [0402]
TP1  TP  [TESTPIN]
TP2  TP  [TESTPIN]
TP3  mikroBUS_LOGO  [LOGO-1]
TP4  TP  [HOLE-250R125]
TP5  TP  [HOLE-250R125]
TP6  TP  [HOLE-250R125]
TP7  TP  [HOLE-250R125]
TP8  TP  [TESTPIN]
TP9  TP  [TESTPIN]
sheet 11_Board_B_Connector
C37  0.1uF  [0402]
CN6  05002HR-14CE  [FFC/0.5mm/14PIN]

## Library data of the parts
C1 C3-C7 C9-C13 C15 C17 C18 C20-C22 C31 C32 C64-C66 = SMALL_CAP
C35 = CAP_NP
J2 J5 = TP_0_v2
L1 L3 L4 L11 L12 = INDUCTOR
R5 = SMALL_R1: Vendor: WALSIN
R6 R15-R17 R19-R21 R23-R25 R28 R34 R35 R55 R69 R70 R88 R89 R99 = SMALL_R1
SB6 = SB
U1 = PARIS_ATM3325_QFN5X5_1: Vendor: ATMOSIC
Y1 = XTAL
Y2 = XTAL-OSC-4P_0
U8 = RF_SWJ_7: Part Number: MM8430-2610; Vendor: MURATA
DS1 DS3 DS12 = LED
S6 S7 = SW-TACT-4P-5
U3 = LIS3DHTR_0
U4 = ENS210-LQFM_2
C34 C37 = SMALL_CAP: Part Number: GRM1555R71H104KE14; Vendor: MURATA
CN5 CN6 = FFC_14PIN_0_2.5MM_D: Part Number: 503480-1400; Vendor: MOLEX
U17 = 24AA014_0
J3 J4 = CONN_SOCKET_08X1: PART_NUMBER: 1x08_Socket_Through_2.54Miscallenous Misc.; Part type: Connector
TP1 TP2 TP4-TP9 = TP_0
TP3 = MikroBUS_LOGO_0: Dialog_Number: 030-740024

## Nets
+5V: J4.7 TP9.1(TP)
AVDD1: C12.1 C13.1 R6.1 U1.1(VDD1A)
AVDD1P: C4.1 R6.2 U1.18(AVDD1P)
DVDD1: C1.1 C3.1 U1.20(DVDD1P) U1.21(DVDD1)
GND_SIGNAL: C1.2 C3.2 C4.2 C5.2 C6.2 C7.2 C9.2 C10.2 C11.2 C12.2 C13.2 C15.1 C17.2 C20.1 C21.1 C22.2 C31.2 C32.2 C34.2 C37.2 C64.2 C66.2 CN5.7 CN5.15 CN5.16 CN6.7 CN6.15 CN6.16 DS1.1(CATHODE) DS3.1(CATHODE) DS12.1(CATHODE) J3.8 J4.8 J5.1(TP) L4.2 R5.1 R15.1 R25.1 R35.1 S6.3 S6.4 SB6.2 TP1.1(TP) TP4.1(TP) TP5.1(TP) TP6.1(TP) TP7.1(TP) TP8.1(TP) U1.15(VSTORE) U1.41(EGND) U3.5(GND) U3.10(RES) U3.12(GND_1) U4.4(VSS) U4.5(VSS_1) U8.1(GND) U8.3(GND) U8.4(GND) U8.6(GND) U17.2(VSS) U17.4(A1) Y2.2(NC) Y2.4(NC)
VBATT: C7.1 C10.1 C11.1 C34.1 C35.2 C37.1 C64.1 CN5.1 CN5.2 CN6.1 CN6.2 J2.1(TP) R20.2 R21.2 R34.2 R88.2 R89.2 R99.2 S7.3 S7.4 TP2.1(TP) U1.6(VDDIO) U1.13(VBAT) U1.28(VDDIO) U17.6(VCC)
VDD_IO: C31.1 C32.1 R20.1 R23.1 R24.1 R69.2 R70.1 U3.1(VDD_IO) U3.14(Vdd) U4.1(VDD)
VDDIOP: C6.1 R16.1 R17.1 U1.17(VDDIOP)
A_Analog: J3.1 U1.8(P4)
Antenna: C18.2 L4.1
B_Button1: R34.1 S6.1 S6.2 U1.31(P19)
B_CS: J3.3 U1.25(P13)
B_INT: CN5.12 CN6.12 J4.2 U1.32(P20)
B_MISO: J3.5 U1.27(P15)
B_MOSI: J3.6 U1.26(P14)
B_PWM: J4.1 U1.40(P30)
B_RST: CN5.13 CN6.13 J3.2 U1.29(P17)
B_RX: CN5.10 CN6.10 J4.3 U1.34(P22)
B_SCK: J3.4 U1.24(P12)
B_SCL: J4.5 R70.2 R99.1 U1.10(P6) U3.4(SCL/SPC) U4.2(SCL) U17.1(SCL)
B_SDA: J4.6 R69.1 R88.1 U1.11(P7) U3.6(SDA/SDI/SDO) U4.3(SDA) U17.3(SDA)
B_TX: CN5.11 CN6.11 J4.4 U1.33(P21)
B_YellowLED: CN5.4 CN6.4 R15.2 R55.2 U1.35(P25)
BUTTON_2: R35.2 S7.1 S7.2 U1.9(P5)
G_INT: U1.30(P18) U3.11(INT1)
LED_1: R19.2 U1.7(P3)
LED_3: R28.2 U1.39(P29)
MB_3V3: C9.1 C15.2 J3.7 R21.1
P0: CN5.6 CN6.6 U1.4(P0)
P1: CN5.8 CN6.8 U1.5(P1)
P27: CN5.14 CN6.14 U1.38(P27)
PWD: C35.1 CN5.3 CN6.3 R5.2 U1.12(PWD)
RFIO: L11.2 U1.2(RFIO)
VAUX: C5.1 R17.2 U1.19(VAUX)
XTALI_16M: U1.37(XTALO_16M) Y2.1(HOT)
XTALI_32K: SB6.1 U1.23(XTALI_32K) Y1.2
XTALO_16M: U1.36(XTALI_16M) Y2.3(HOT)
XTALO_32K: U1.22(XTALO_32K) Y1.1
N16873328: L1.1 U1.14(LEXT1)
N16873338: L1.2 U1.16(LEXT2)
N16893506: C17.1 R16.2 U1.3(VDDPA)
N17101173: C18.1 C66.1 U8.5(OUT)
N17101247: C22.1 L3.2
N17103007: R23.2 R25.2 U3.7(SDO/SA0)
N17103021: R24.2 U3.8(CS)
N17202674: C65.2 L3.1 U8.2(IN)
N17202748: C21.2 L11.1 L12.2
N17202795: C20.2 C65.1 L12.1
N17215838: DS1.2(ANODE) R19.1
N17215912: DS3.2(ANODE) R28.1
N17218343: DS12.2(ANODE) R55.1
N17218729: R89.1 U17.5(A0)

Not connected (* = marked no-connect by the designer): CN5 5* 9*; CN6 5* 9*; U3 2(NC)* 3(NC_1)* 9(INT2)* 13(ADC3)* 15(ADC2)* 16(ADC1)*

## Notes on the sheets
sheet 1
- ATM3325 Tag Reference Design
- Release Date
- Revision
- Design Eng.
- Design Notes
- 08/22/2022
- V0
- Yancey Yang
- Initial release
- 01/06/2023
- V1
- Yancey Yang
- Update the RFIO and antenna matching value
- 05/16/2023
- V2
- Yancey Yang
- Update the RFIO value
- - L11 is changed to 5.1nH(TDK)
- - L2 is changed to 3nH(TDK)
- - C20 is changed to 1.2pF
- - C65 is changed to 22pF
- R17=NC, R16=0 ohm, C6=1uF, C17=1uF, R70=10K
- Atmosic Technologies, Inc
- 2105 South Bascom Avenue, Suite 220
  Campbell, CA 95008
- ATMOSIC TECHNOLOGIES INC
- Atmosic Technologies Proprietary and Confidential
sheet 2
- Block Diagram
- Tag
- Temp/Humidity Sensor
- Accelerometer
- ATM3325
- A
- LEDs(red and green)
- Firmware
  programming
  interface
- Button
- CR2032
- Firmware
  programming
  interface
- MikroBus
- LED and
   Button
- Notes:
  Board_A and Board_B can be broken-off.
- MikroBus
- BIDS
- LED(yellow)
- B
- Button
- Firmware
  programming
  interface
- Expansion board
sheet 3
- Block Diagram - A
- Board-B
- BLE Tx/Rx
  Match
- RFIO
- RF con.
  MM8430-2610(SWD)
- For the control of yellow LED
- Yellow LED
- P25
- For the control of button
- Button
- P19
- SCL
- P6
- SDA
- P7
- PWM(P30)
- G_INT
- INT(P20)
- P18
- Motion sensor
- RHT sensor
- UART0_RX(P22)
- UART0_TX(P21)
- P5
- Long push: ATM33 enters SOC_OFF mode
  Single push: ATM33 cold start into active
- Button
- SCL(P6)
- SDA(P7)
- P3
- Red LED
- Red/green color
   -For operation/battery status.
   -LED on every 30 secs
- P29
- Green LED
- ATM3325
- VDDPA
- VDDIOP
- Board-B
- VDDIO
- VDDIO
- Firmware program
  &Debug interface
- VBAT
- CR2032
- VBAT
- PWD
- P25(BBOOT)
- P0(SWDCLK)
- Board-B
- P1(SWDIO)
- MOSI(P14)
- P20(UART0_CTS)
- MISO(P15)
- P17(UART0_RTS)
- SCK(P12)
- P21(UART0_TX)
- CS(P13)
- P22(UART0_RX)
- RST(P17)
- ATMOSIC TECHNOLOGIES INC
- AN(P4)
- P27(UART1_TX)
sheet 4
- Block Diagram - B
- P25
- Yellow LED
- External
- Button
- P19
- PWM
- P30
- 5V
- INT
- P20
- RX
- P22
- TX
- P21
- SCL
- P6
- MikroBUS
- SDA
- P7
- From Board A
- BIDS
- MOSI
- P14
- VDDIO
- MISO
- P15
- VBAT
- Firmware program
  &Debug interface
- SCK
- P12
- PWD
- CS
- P13
- RST
- P17
- P25(BBOOT)
- 3.3V
- P0(SWDCLK)
- AN
- P4
- P1(SWDIO)
- P20(UART0_CTS)
- VBAT
- P17(UART0_RTS)
- P21(UART0_TX)
- P22(UART0_RX)
- P27(UART1_TX)
sheet 5
- Board A
- 16MHz XTAL
- Change C12 to 22uF if needs
  to operate below -20 Celsius
- Battary and power-on reset
- J2 and J5 are connectors for CR2032
- Benign boot
- 5X5 QFN
- ATMOSIC TECHNOLOGIES INC
- Atmosic Technologies Proprietary and Confidential
sheet 6
- Board A
- BLE front-end match
- Note:
  For inductors, use MHQ series from TDK.
  For capacitors, use Johanson
- ATMOSIC TECHNOLOGIES INC
- Atmosic Technologies Proprietary and Confidential
sheet 7
- Board A
- GPIO MUX
- TEMP/HUM SENSOR
- The I2C slave device address of ENS210: 0x43
- PUSH BUTTONS
- MOTION SENSOR
- PTS645 SMD
- LEDS
- SA0: I2C less significant bit of the device address.
  High: 0x19
  Default: input with internal pull-up
- ATMOSIC TECHNOLOGIES INC
sheet 8
- Board A
- GPIO MUX
- JTAG PROGRAMMING
- GPIOs to Board_B(On Board B)
- ATMOSIC TECHNOLOGIES INC
sheet 9
- Board B
- LED
- BIDS (1Kbits)
- The I2C slave device address: 0x51
- 24AA014
- PUSH BUTTON
- PTS645 SMD
sheet 10
- Board B
- +5V
- GND
- VBATT
- GND
- AN
  RST
  CS
  SCK
  MISO
  MOSI
  +3.3V
  GND
- PWM
  INT
  RX
  TX
  SCL
  SDA
  +5V
  GND
- MikroBUS SOCKETS
- GND
- GND
- GND
- GND
- ATMOSIC TECHNOLOGIES INC
sheet 11
- Board B
- GPIO MUX
- JTAG PROGRAMMING
